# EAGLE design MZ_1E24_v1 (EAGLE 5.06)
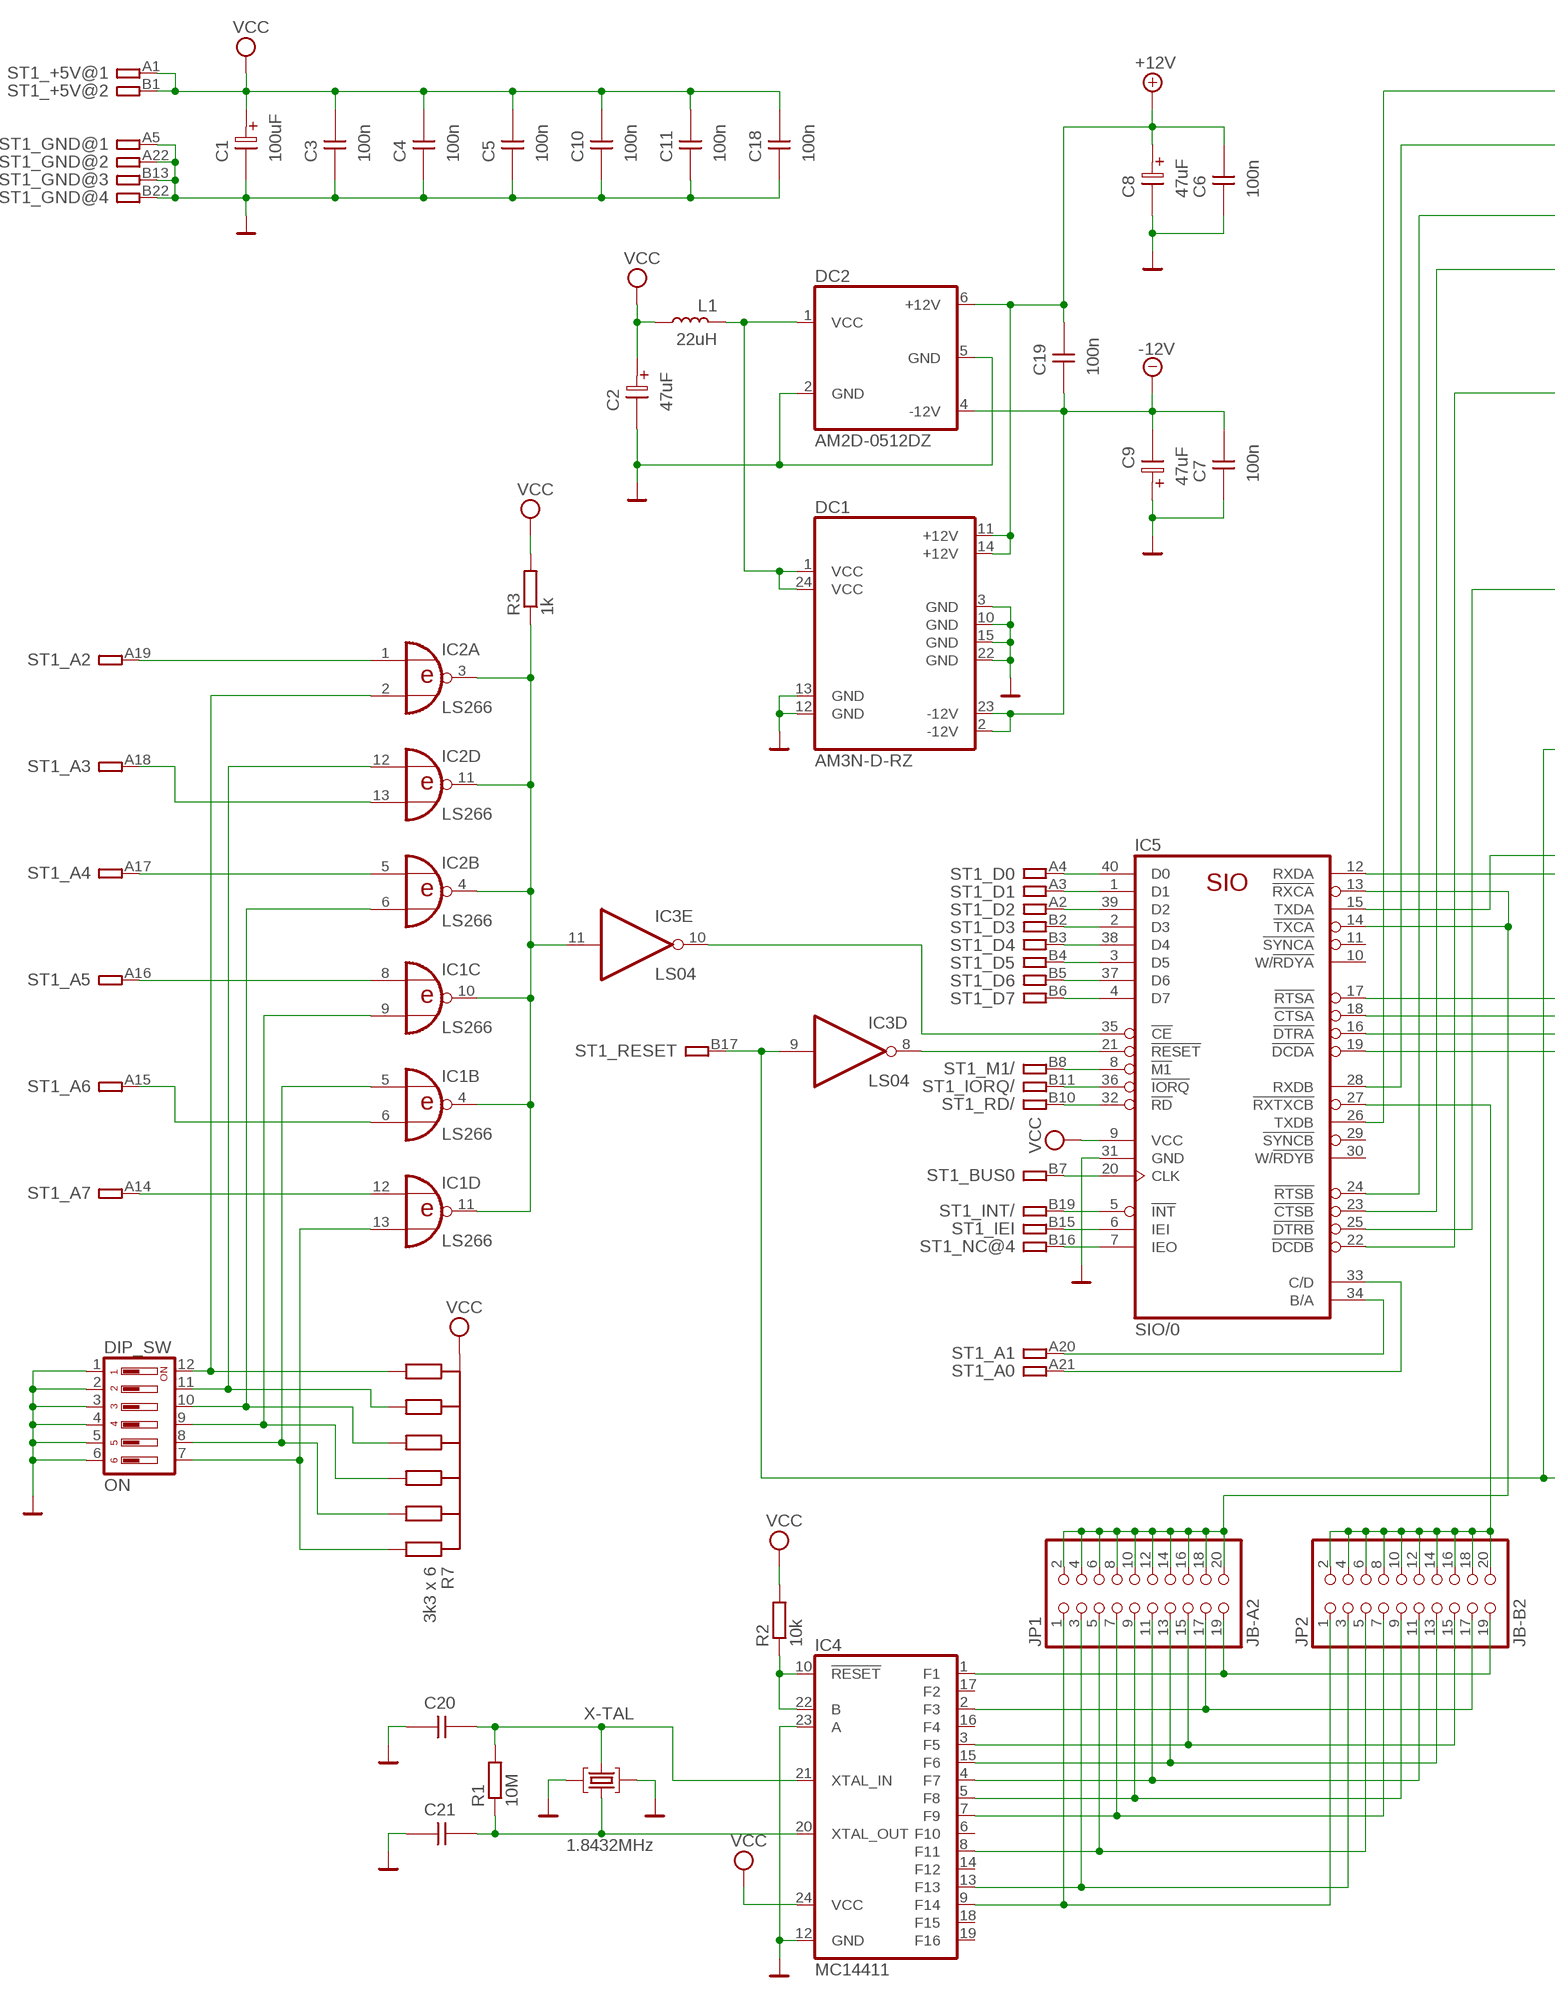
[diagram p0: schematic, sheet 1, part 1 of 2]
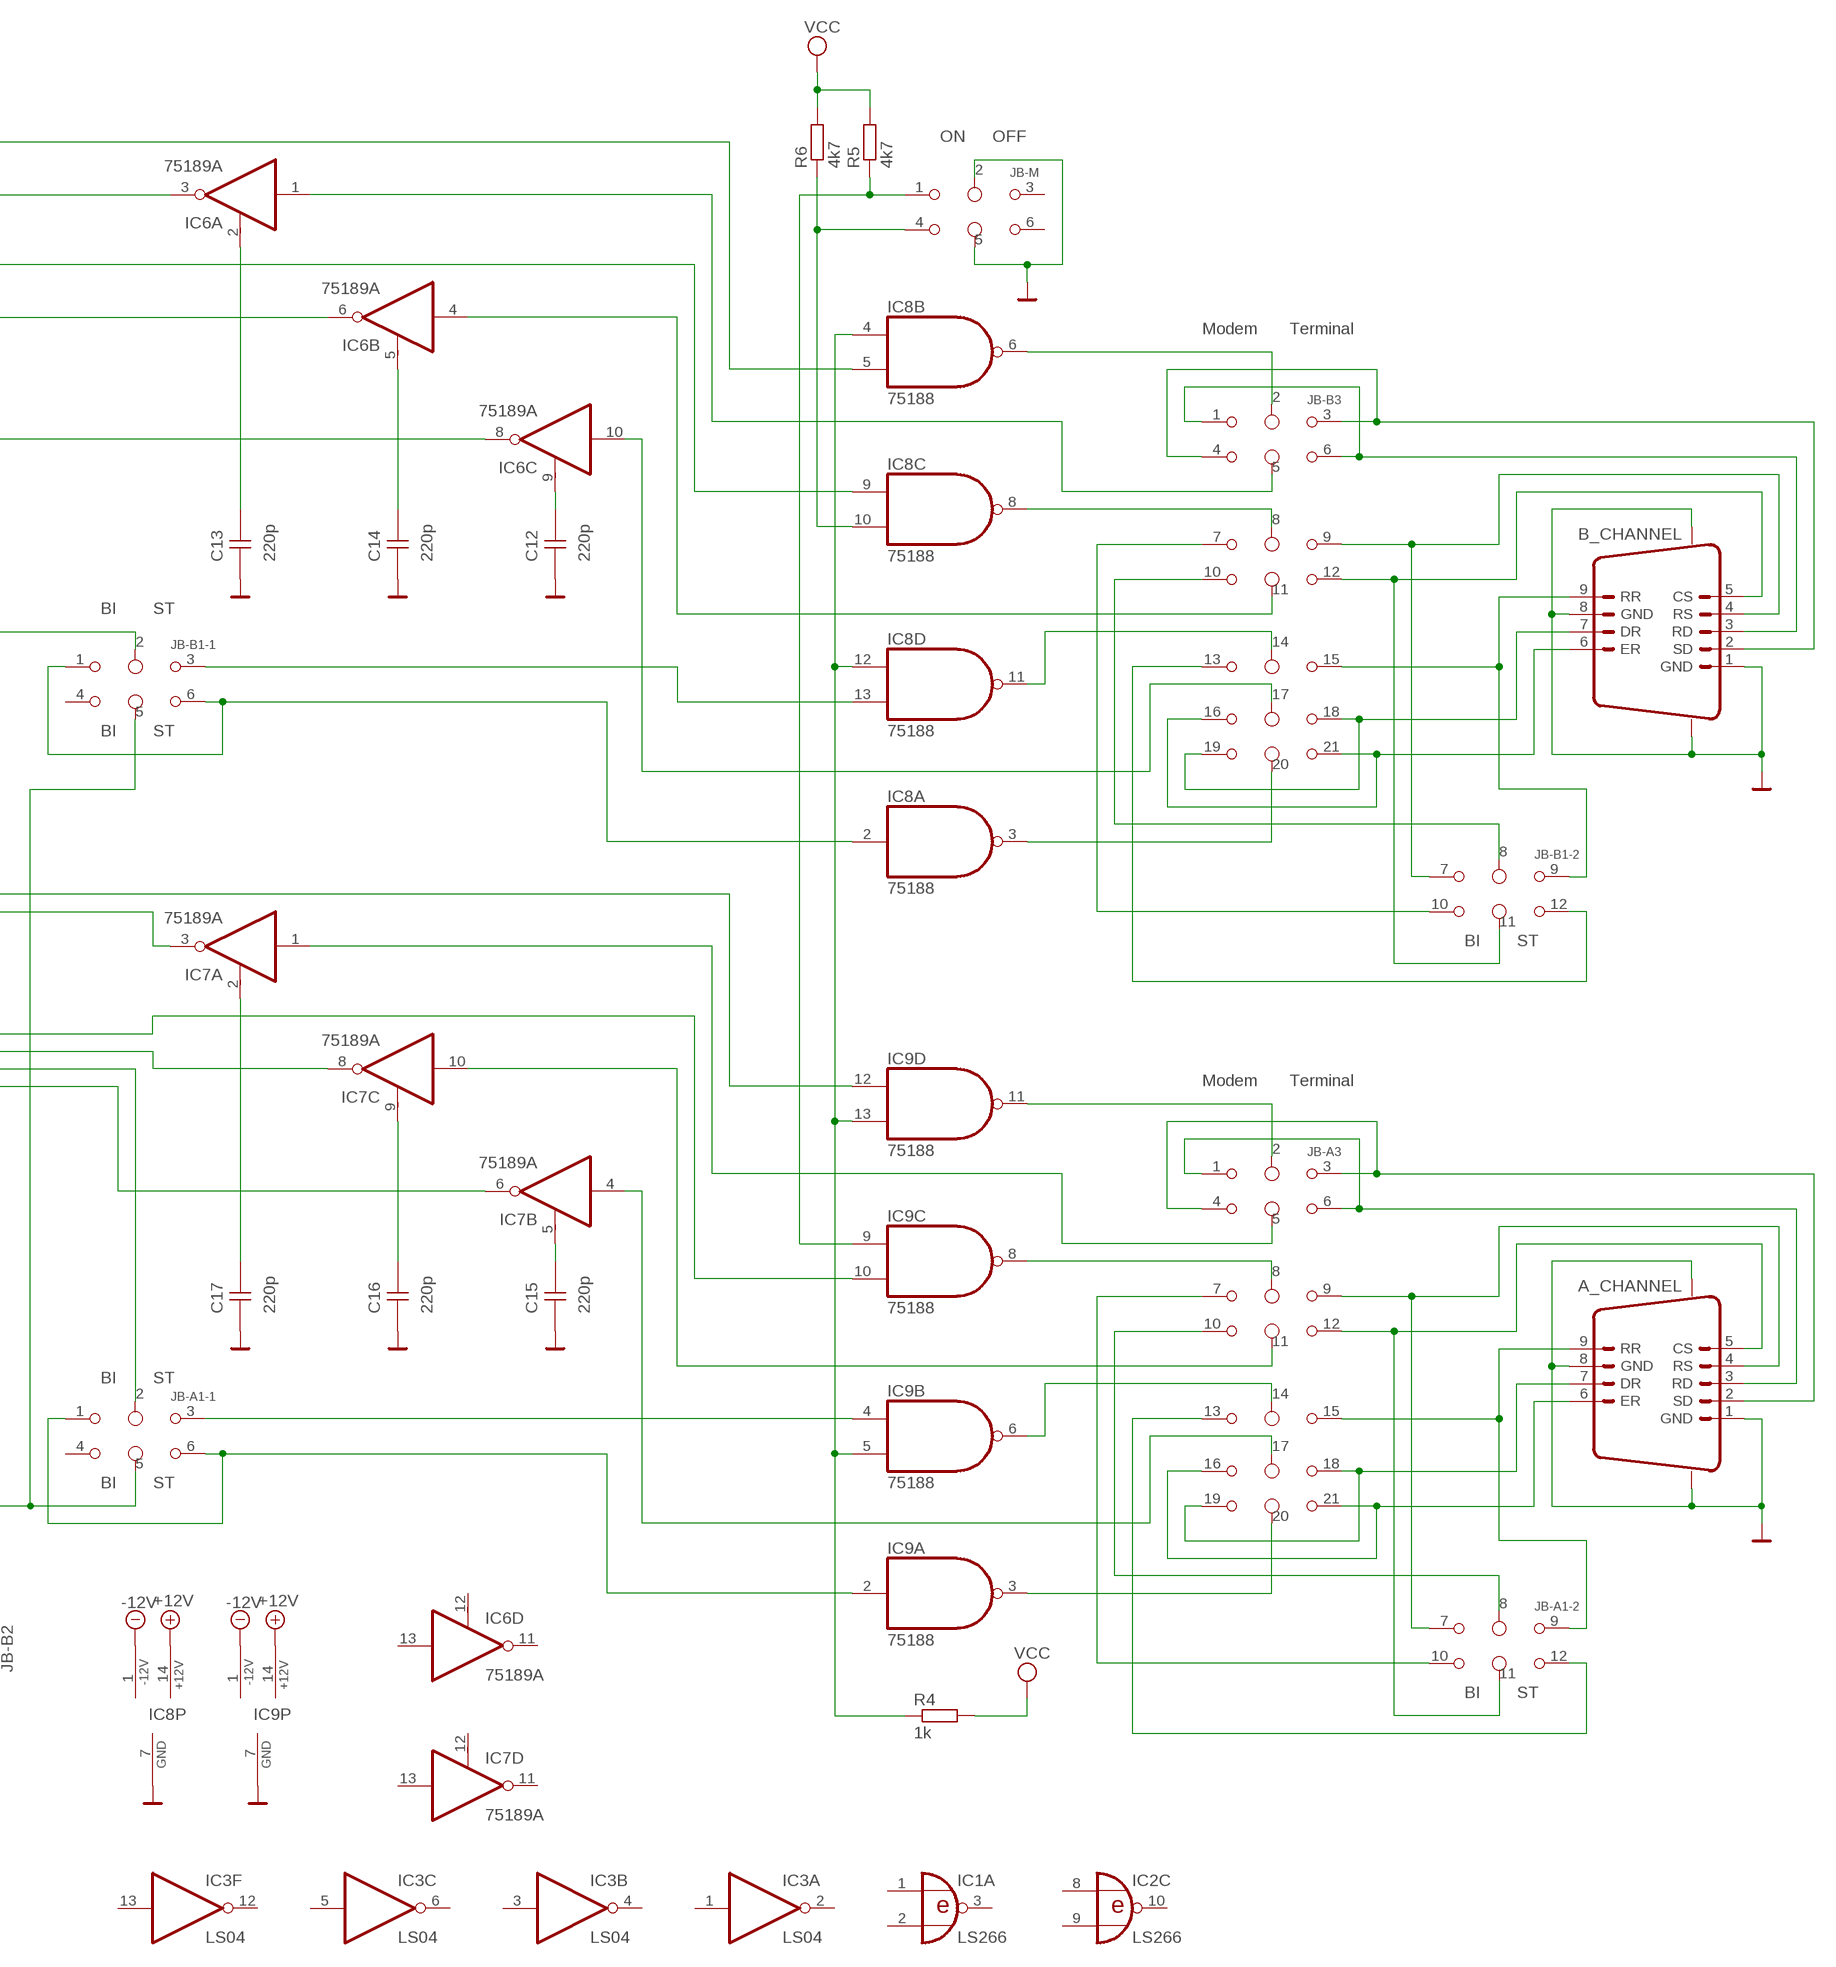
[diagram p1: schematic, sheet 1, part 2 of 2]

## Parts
A_CHANNEL  RS232_PC"  [RS232_F]
B_CHANNEL  RS232_PC"  [RS232_F]
C1  100uF  E6,3X11  [E63]
C2  47uF  E6,3X11  [E63]
C3  100n  CK  [CK]
C4  100n  CK  [CK]
C5  100n  CK  [CK]
C6  100n  CK  [CK]
C7  100n  CK  [CK]
C8  47uF  E6,3X11  [E63]
C9  47uF  E6,3X11  [E63]
C10  100n  CK  [CK]
C11  100n  CK  [CK]
C12  220p  CK  [CK]
C13  220p  CK  [CK]
C14  220p  CK  [CK]
C15  220p  CK  [CK]
C16  220p  CK  [CK]
C17  220p  CK  [CK]
C18  100n  CK  [CK]
C19  100n  CK  [CK]
C20  CK  [CK]
C21  CK  [CK]
DC1  AM3N-D-RZ  DC-DC_AM3N  [DC-DC_AM3N]
DC2  AM2D-0512DZ  DC-DC_AM1D  [DC-DC_AM1D]
DIP_SW  ON  SWITCH-DIL_DIP06YL  [SWITCH-DIL_DIP06YL]
IC1  LS266  74266  [DIL14]
IC2  LS266  74266  [DIL14]
IC3  LS04  74LS04N  [EU_DIL14]
IC4  MC14411  [DIL24]
IC5  SIO/0  Z80SIO0  [DIL40]
IC6  75189A  1489  [DIL14]
IC7  75189A  1489  [DIL14]
IC8  75188  1488N  [INTERFACE_DIL14]
IC9  75188  1488N  [INTERFACE_DIL14]
JB-A1  PINHD-4X3  [PINHD-4X3]
JB-A3  JB-A3  PINHD-7X3A  [PINHD-7X3A]
JB-B1  PINHD-4X3B  [PINHD-4X3B]
JB-B3  JB-B3  PINHD-7X3B  [PINHD-7X3B]
JB-M  JB-M  PINHD-2X3  [PINHD-2X3]
JP1  JB-A2  PINHD-2X10A  [PINHD-2X10A]
JP2  JB-B2  PINHD-2X10  [PINHD-2X10]
L1  22uH  L  [L]
R1  10M  R-EU_0204/5  [RCL_0204/5]
R2  10k  R-EU_0204/5  [RCL_0204/5]
R3  1k  R-EU_0204/5  [RCL_0204/5]
R4  1k  R-EU_0204/5  [RCL_0204/5]
R5  4k7  R-EU_0204/5  [RCL_0204/5]
R6  4k7  R-EU_0204/5  [RCL_0204/5]
R7  3k3 x 6  RR6X  [RR6X]
ST1  MZ800BUSSHORTN  [MZ800BUSSHORTN]
X-TAL  1.8432MHz  HC49TL-H  [HC49TL-H]

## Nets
+12V: C6.2 C8.1 C19.2 DC1.11(+12V) DC1.14(+12V) DC2.6(+12V) IC8.14(P:+12V) IC9.14(P:+12V)
-12V: C7.2 C9.2 C19.1 DC1.2(-12V) DC1.23(-12V) DC2.4(-12V) IC8.1(P:-12V) IC9.1(P:-12V)
A0: IC5.33(C/D) ST1.A21
A1: IC5.34(B/A) ST1.A20
A2: IC2.1(A:I0) ST1.A19
A4: IC2.5(B:I0) ST1.A17
A5: IC1.8(C:I0) ST1.A16
A7: IC1.12(D:I0) ST1.A14
A_CHANNEL: A_CHANNEL.7(DR) JB-A3.18 JB-A3.19
A_CHANNEL1: B_CHANNEL.7(DR) JB-B3.18 JB-B3.19
BUS0: IC5.20(CLK) ST1.B7
D0: IC5.40(D0) ST1.A4
D1: IC5.1(D1) ST1.A3
D2: IC5.39(D2) ST1.A2
D3: IC5.2(D3) ST1.B2
D4: IC5.38(D4) ST1.B3
D5: IC5.3(D5) ST1.B4
D6: IC5.37(D6) ST1.B5
D7: IC5.4(D7) ST1.B6
EXTINT: IC5.5(!INT) ST1.B19
GND: A_CHANNEL.1(GND) A_CHANNEL.8(GND) A_CHANNEL.P$1(GND) A_CHANNEL.P$2(GND) B_CHANNEL.1(GND) B_CHANNEL.8(GND) B_CHANNEL.P$1(GND) B_CHANNEL.P$2(GND) C1.2 C2.2 C3.1 C4.1 C5.1 C6.1 C7.1 C8.2 C9.1 C10.1 C11.1 C12.1 C13.1 C14.1 C15.1 C16.1 C17.1 C18.1 C20.1 C21.1 DC1.3(GND) DC1.10(GND) DC1.12(GND) DC1.13(GND) DC1.15(GND) DC1.22(GND) DC2.2(GND) DC2.5(GND) DIP_SW.1 DIP_SW.2 DIP_SW.3 DIP_SW.4 DIP_SW.5 DIP_SW.6 IC4.12(GND) IC4.23(A) IC5.31(GND) IC8.7(P:GND) IC9.7(P:GND) JB-M.2 JB-M.5 ST1.A5 ST1.A22 ST1.B13 ST1.B22 X-TAL.3 X-TAL.4 ; supply symbol labelled gnd
IEI: IC5.6(IEI) ST1.B15
IEO: IC5.7(IEO) ST1.B16
IORQ: IC5.36(!IORQ) ST1.B11
M1: IC5.8(!M1) ST1.B8
N$1: IC1.4(B:O) IC1.10(C:O) IC1.11(D:O) IC2.3(A:O) IC2.4(B:O) IC2.11(D:O) IC3.11(E:I) R3.1
N$2: IC3.8(D:O) IC5.21(!RESET)
N$3: IC5.27(!RXTXCB) JP2.2 JP2.4 JP2.6 JP2.8 JP2.10 JP2.12 JP2.14 JP2.16 JP2.18 JP2.20
N$4: IC5.13(!RXCA) IC5.14(!TXCA) JP1.2 JP1.4 JP1.6 JP1.8 JP1.10 JP1.12 JP1.14 JP1.16 JP1.18 JP1.20
N$5: C21.2 IC4.20(XTAL_OUT) R1.1 X-TAL.1
N$6: C20.2 IC4.21(XTAL_IN) R1.2 X-TAL.2
N$7: DIP_SW.12 IC2.2(A:I1) R7.7
N$8: DIP_SW.11 IC2.12(D:I0) R7.6
N$9: DIP_SW.10 IC2.6(B:I1) R7.5
N$10: DIP_SW.9 IC1.9(C:I1) R7.4
N$11: DIP_SW.8 IC1.5(B:I0) R7.3
N$12: DIP_SW.7 IC1.13(D:I1) R7.2
N$13: C15.2 IC7.5(B:RC)
N$14: C16.2 IC7.9(C:RC)
N$15: C17.2 IC7.2(A:RC)
N$16: C12.2 IC6.9(C:RC)
N$17: C14.2 IC6.5(B:RC)
N$18: C13.2 IC6.2(A:RC)
N$19: IC4.9(F14) JP1.1 JP2.1
N$20: IC4.13(F13) JP1.3 JP2.3
N$21: IC4.8(F11) JP1.5 JP2.5
N$22: IC4.7(F9) JP1.7 JP2.7
N$23: IC4.5(F8) JP1.9 JP2.9
N$24: IC4.4(F7) JP1.11 JP2.11
N$25: IC4.15(F6) JP1.13 JP2.13
N$26: IC4.3(F5) JP1.15 JP2.15
N$27: IC4.2(F3) JP1.17 JP2.17
N$28: IC4.1(F1) JP1.19 JP2.19
N$29: IC3.10(E:O) IC5.35(!CE)
N$30: IC4.10(!RESET) IC4.22(B) R2.1
N$31: IC9.6(B:O) JB-A3.14
N$32: DC1.1(VCC) DC1.24(VCC) DC2.1(VCC) L1.1
N$33: IC8.2(A:I) JB-B1.1 JB-B1.6
N$34: IC8.4(B:I0) IC8.12(D:I0) IC9.5(B:I1) IC9.13(D:I1) R4.1
N$35: IC9.3(A:O) JB-A3.20
N$37: A_CHANNEL.6(ER) JB-A3.16 JB-A3.21
N$38: IC7.4(B:I) JB-A3.17
N$39: IC9.8(C:O) JB-A3.8
N$40: IC9.11(D:O) JB-A3.2
N$41: A_CHANNEL.3(RD) JB-A3.1 JB-A3.6
N$42: A_CHANNEL.2(SD) JB-A3.3 JB-A3.4
N$43: IC7.1(A:I) JB-A3.5
N$44: IC7.10(C:I) JB-A3.11
N$45: A_CHANNEL.4(RS) JB-A1.7 JB-A3.9
N$46: A_CHANNEL.5(CS) JB-A1.11 JB-A3.12
N$47: A_CHANNEL.9(RR) JB-A1.9 JB-A3.15
N$48: JB-A1.12 JB-A3.13
N$49: IC5.15(TXDA) IC9.12(D:I0)
N$50: JB-A1.10 JB-A3.7
N$51: JB-A1.8 JB-A3.10
N$52: IC5.12(RXDA) IC7.3(A:O)
N$53: IC5.17(!RTSA) IC9.10(C:I1)
N$54: IC9.4(B:I0) JB-A1.3
N$55: IC5.18(!CTSA) IC7.8(C:O)
N$56: IC5.19(!DCDA) IC7.6(B:O)
N$57: IC9.2(A:I) JB-A1.1 JB-A1.6
N$58: IC5.16(!DTRA) JB-A1.2
N$59: IC2.13(D:I1) ST1.A18
N$60: IC1.6(B:I1) ST1.A15
N$67: IC8.13(D:I1) JB-B1.3
N$75: IC8.10(C:I1) JB-M.4 R6.1
N$80: IC9.9(C:I0) JB-M.1 R5.1
N$84: IC8.3(A:O) JB-B3.20
N$85: B_CHANNEL.6(ER) JB-B3.16 JB-B3.21
N$86: IC6.10(C:I) JB-B3.17
N$87: IC8.11(D:O) JB-B3.14
N$88: IC8.8(C:O) JB-B3.8
N$89: IC8.6(B:O) JB-B3.2
N$90: B_CHANNEL.3(RD) JB-B3.1 JB-B3.6
N$91: B_CHANNEL.2(SD) JB-B3.3 JB-B3.4
N$92: IC6.1(A:I) JB-B3.5
N$93: IC6.4(B:I) JB-B3.11
N$94: B_CHANNEL.4(RS) JB-B1.7 JB-B3.9
N$95: B_CHANNEL.5(CS) JB-B1.11 JB-B3.12
N$96: B_CHANNEL.9(RR) JB-B1.9 JB-B3.15
N$97: JB-B1.12 JB-B3.13
N$98: JB-B1.10 JB-B3.7
N$99: JB-B1.8 JB-B3.10
N$100: IC5.26(TXDB) IC8.5(B:I1)
N$101: IC5.28(RXDB) IC6.3(A:O)
N$102: IC5.24(!RTSB) IC8.9(C:I0)
N$104: IC5.23(!CTSB) IC6.6(B:O)
N$105: IC5.22(!DCDB) IC6.8(C:O)
N$107: IC5.25(!DTRB) JB-B1.2
RD: IC5.32(!RD) ST1.B10
RESET: IC3.9(D:I) JB-A1.5 JB-B1.5 ST1.B17
VCC: C1.1 C2.1 C3.2 C4.2 C5.2 C10.2 C11.2 C18.2 IC4.24(VCC) IC5.9(VCC) L1.2 R2.2 R3.2 R4.2 R5.2 R6.2 R7.1 ST1.A1 ST1.B1
Unconnected: IC1.1(A:I0) IC1.2(A:I1) IC1.3(A:O) IC2.8(C:I0) IC2.9(C:I1) IC2.10(C:O) IC3.1(A:I) IC3.2(A:O) IC3.3(B:I) IC3.4(B:O) IC3.5(C:I) IC3.6(C:O) IC3.12(F:O) IC3.13(F:I) IC4.6(F10) IC4.14(F12) IC4.16(F4) IC4.17(F2) IC4.18(F15) IC4.19(F16) IC5.10(W/!RDYA) IC5.11(!SYNCA) IC5.29(!SYNCB) IC5.30(W/!RDYB) IC6.11(D:O) IC6.12(D:RC) IC6.13(D:I) IC7.11(D:O) IC7.12(D:RC) IC7.13(D:I) JB-A1.4 JB-B1.4 JB-M.3 JB-M.6 ST1.A6 ST1.A7 ST1.A8 ST1.A9 ST1.A10 ST1.A11 ST1.A12 ST1.A13 ST1.B9 ST1.B12 ST1.B14 ST1.B18 ST1.B20 ST1.B21

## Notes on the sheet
- ON | OFF
- Modem | Terminal
- BI | ST
- BI | ST
- BI | ST
- Modem | Terminal
- BI | ST
- BI | ST
- BI | ST

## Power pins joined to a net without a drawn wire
GND: IC1.7(P:GND) IC2.7(P:GND) IC3.7(P:GND) IC6.7(P:GND) IC7.7(P:GND)
VCC: IC1.14(P:VCC) IC2.14(P:VCC) IC3.14(P:VCC) IC6.14(P:VCC) IC7.14(P:VCC)

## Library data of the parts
A_CHANNEL B_CHANNEL = MZ_1E24:RS232_PC
C1 C2 C8 C9 = MZ_1E24:E6,3X11
C3-C7 C10-C21 = MZ_1E24:CK
DC1 = MZ_1E24:DC-DC_AM3N
DC2 = MZ_1E24:DC-DC_AM1D
DIP_SW = MZ_1E24:SWITCH-DIL_DIP06YL: DIL/CODE SWITCH
IC1 IC2 = MZ_1E24:74*266: Quadruple EXCLUSIVE-NOR (XNOR), open-collector
IC3 = MZ_1E24:74*04: Hex INVERTER
IC4 = MZ_1E24:MC14411
IC5 = MZ_1E24:Z80SIO0: Z80 FAMILY DEVICE
IC6 IC7 = MZ_1E24:14*89: Quad line receivers BUFFER,
IC8 IC9 = MZ_1E24:14*88: Quad 2-input NAND gate
JB-A1 JB-B1 = MZ_1E24:PINHD-4X3
JB-A3 JB-B3 = MZ_1E24:PINHD-7X3
JB-M = MZ_1E24:PINHD-2X3
JP1 JP2 = MZ_1E24:PINHD-2X10: PIN HEADER
L1 = MZ_1E24:L
R1-R6 = MZ_1E24:R-EU_: RESISTOR, European symbol
R7 = MZ_1E24:RR6X
ST1 = MZ_1E24:MZ800BUSSHORT: 44-bit BUS for MZ800
X-TAL = MZ_1E24:HC49TL-H: CRYSTAL

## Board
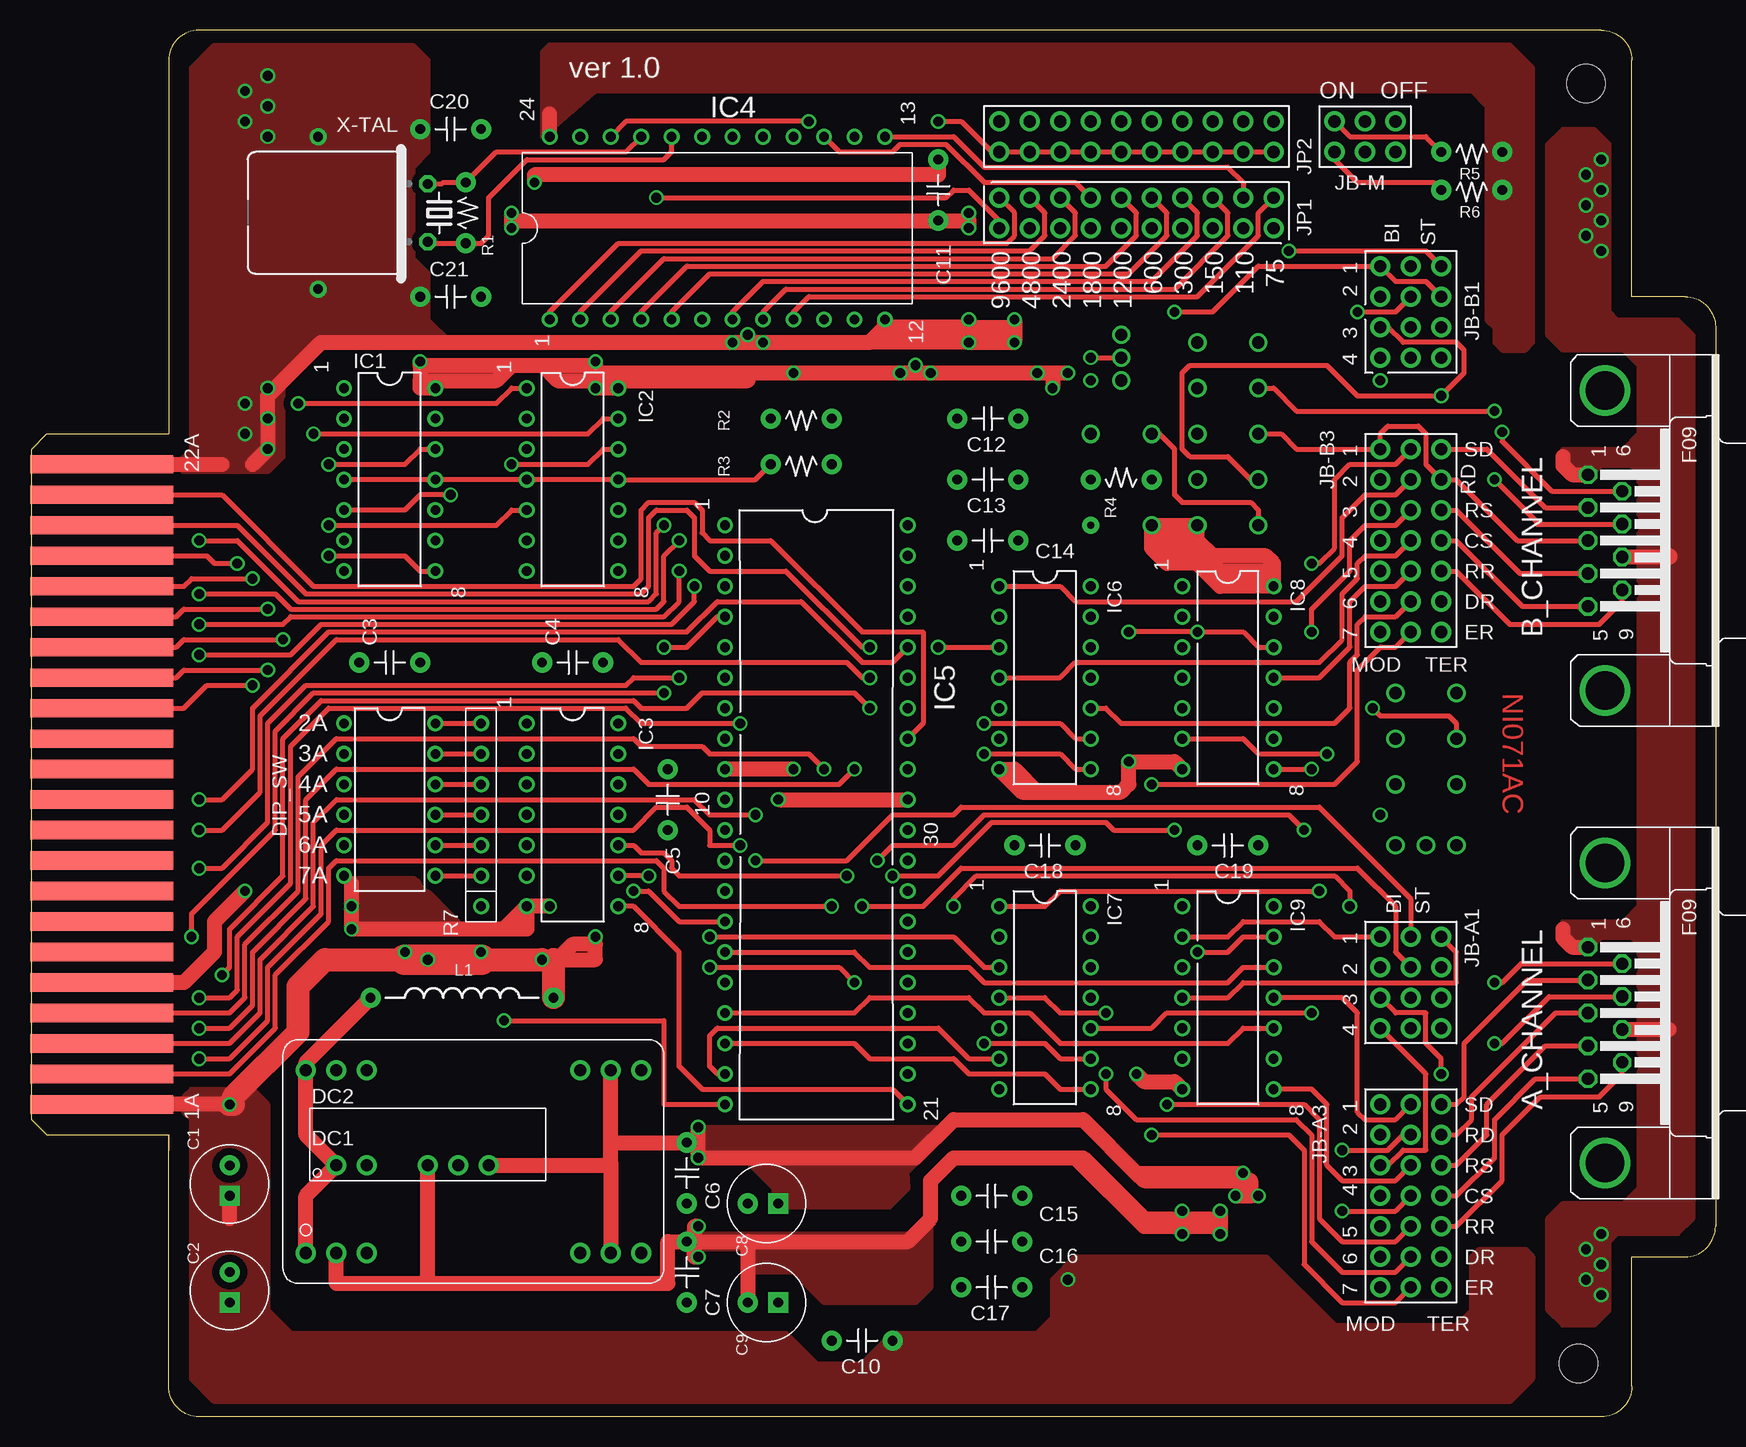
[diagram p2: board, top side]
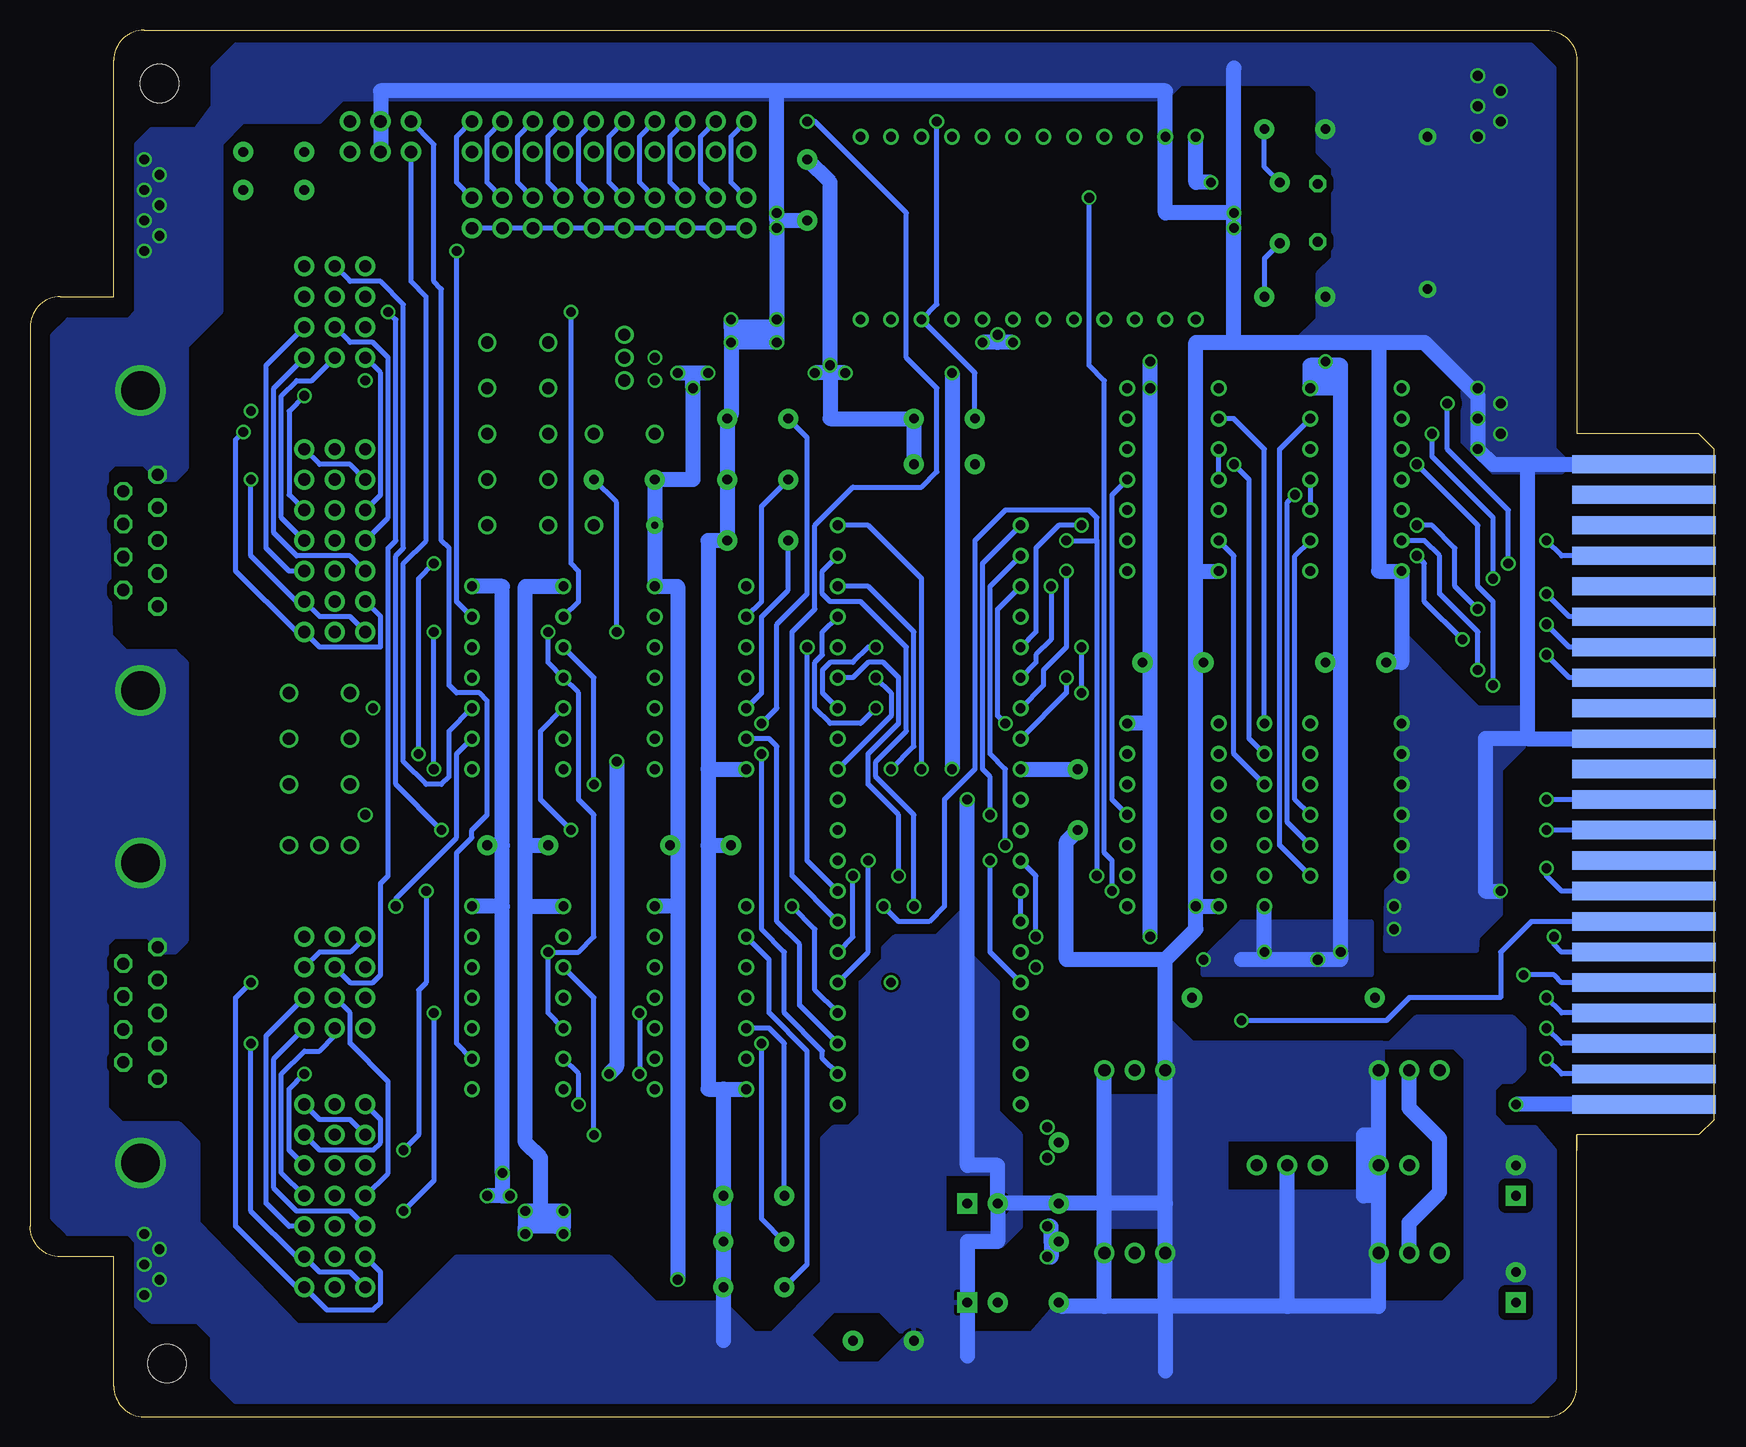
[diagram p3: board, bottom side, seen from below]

Size 140.34 x 115.57 mm. Coordinates in mm from the lower left corner, seen from the top.
Outline: 11.43,89.53 11.43,113.03 arc-90 13.97,115.57 130.81,115.57 arc-90 133.35,113.03 133.35,93.34 137.8,93.34 arc-90 140.34,90.81 140.34,15.88 arc-90 137.8,13.34 133.35,13.34 133.35,2.54 arc-90 130.81,0 13.97,0 arc-90 11.43,2.54 11.43,23.5
Copper layers (1*16): Top 0.035mm / dielectric 1.5mm / Bottom 0.035mm
Design rules "MZ_1E24 *": minimum track width 6mil, minimum drill 12mil, track to track 8mil, track to pad 8mil, pad to pad 8mil, via to via 8mil, smd to smd 0mil, copper to edge 10mil, drill to drill 10mil, minimum pad ring 10mil, minimum via ring 6mil, stop-mask expansion 2mil, vias tented up to drill 100mil, thermal gap 10mil
Holes 3.2 mm at 129.54,111.12 128.91,4.45

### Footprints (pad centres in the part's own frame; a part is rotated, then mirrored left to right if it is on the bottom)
RS232_F = drill 1.016 octagon: 1 -5.486,0.794; 2 -2.743,0.794; 3 0,0.794; 4 2.743,0.794; 5 5.486,0.794; 6 -4.115,3.651; 7 -1.372,3.651; 8 1.371,3.651; 9 4.115,3.651 | drill 3.2 round: P$1 -12.502,2.223; P$2 12.502,2.223
E63 = drill 0.813 pad 1.676 square: 1 0,0 | drill 0.813 pad 1.676 round: 2 2.54,0
CK = drill 0.813 pad 1.676 round: 1 0,0; 2 5.08,0
DC-DC_AM3N = drill 1.016 pad 1.676 round: 1 1.905,2.54; 2 4.445,2.54; 3 6.985,2.54; 10 24.765,2.54; 11 27.305,2.54; 12 29.845,2.54; 13 29.845,17.78; 14 27.305,17.78; 15 24.765,17.78; 22 6.985,17.78; 23 4.445,17.78; 24 1.905,17.78
DC-DC_AM1D = drill 1.016 pad 1.676 round: 1 2.223,1.27; 2 4.763,1.27; 4 9.842,1.27; 5 12.383,1.27; 6 14.922,1.27
SWITCH-DIL_DIP06YL = drill 0.813 round: 1 -6.35,-3.81; 2 -3.81,-3.81; 3 -1.27,-3.81; 4 1.27,-3.81; 5 3.81,-3.81; 6 6.35,-3.81; 7 6.35,3.81; 8 3.81,3.81; 9 1.27,3.81; 10 -1.27,3.81; 11 -3.81,3.81; 12 -6.35,3.81
DIL14 = drill 0.813 round: 1 -7.62,-3.81; 2 -5.08,-3.81; 3 -2.54,-3.81; 4 0,-3.81; 5 2.54,-3.81; 6 5.08,-3.81; 7 7.62,-3.81; 8 7.62,3.81; 9 5.08,3.81; 10 2.54,3.81; 11 0,3.81; 12 -2.54,3.81; 13 -5.08,3.81; 14 -7.62,3.81
EU_DIL14 = drill 0.813 round: 1 -7.62,-3.81; 2 -5.08,-3.81; 3 -2.54,-3.81; 4 0,-3.81; 5 2.54,-3.81; 6 5.08,-3.81; 7 7.62,-3.81; 8 7.62,3.81; 9 5.08,3.81; 10 2.54,3.81; 11 0,3.81; 12 -2.54,3.81; 13 -5.08,3.81; 14 -7.62,3.81
DIL24 = drill 0.813 round: 1 -13.97,-7.62; 2 -11.43,-7.62; 3 -8.89,-7.62; 4 -6.35,-7.62; 5 -3.81,-7.62; 6 -1.27,-7.62; 7 1.27,-7.62; 8 3.81,-7.62; 9 6.35,-7.62; 10 8.89,-7.62; 11 11.43,-7.62; 12 13.97,-7.62; 13 13.97,7.62; 14 11.43,7.62; 15 8.89,7.62; 16 6.35,7.62; 17 3.81,7.62; 18 1.27,7.62; 19 -1.27,7.62; 20 -3.81,7.62; 21 -6.35,7.62; 22 -8.89,7.62; 23 -11.43,7.62; 24 -13.97,7.62
DIL40 = drill 0.813 round: 1 -24.13,-7.62; 2 -21.59,-7.62; 3 -19.05,-7.62; 4 -16.51,-7.62; 5 -13.97,-7.62; 6 -11.43,-7.62; 7 -8.89,-7.62; 8 -6.35,-7.62; 9 -3.81,-7.62; 10 -1.27,-7.62; 11 1.27,-7.62; 12 3.81,-7.62; 13 6.35,-7.62; 14 8.89,-7.62; 15 11.43,-7.62; 16 13.97,-7.62; 17 16.51,-7.62; 18 19.05,-7.62; 19 21.59,-7.62; 20 24.13,-7.62; 21 24.13,7.62; 22 21.59,7.62; 23 19.05,7.62; 24 16.51,7.62; 25 13.97,7.62; 26 11.43,7.62; 27 8.89,7.62; 28 6.35,7.62; 29 3.81,7.62; 30 1.27,7.62; 31 -1.27,7.62; 32 -3.81,7.62; 33 -6.35,7.62; 34 -8.89,7.62; 35 -11.43,7.62; 36 -13.97,7.62; 37 -16.51,7.62; 38 -19.05,7.62; 39 -21.59,7.62; 40 -24.13,7.62
INTERFACE_DIL14 = drill 0.813 round: 1 -7.62,-3.81; 2 -5.08,-3.81; 3 -2.54,-3.81; 4 0,-3.81; 5 2.54,-3.81; 6 5.08,-3.81; 7 7.62,-3.81; 8 7.62,3.81; 9 5.08,3.81; 10 2.54,3.81; 11 0,3.81; 12 -2.54,3.81; 13 -5.08,3.81; 14 -7.62,3.81
PINHD-4X3 = drill 1.016 pad 1.676 round: 1 -2.54,3.81; 2 0,3.81; 3 2.54,3.81; 4 -2.54,1.27; 5 0,1.27; 6 2.54,1.27; 7 -2.54,-1.27; 8 0,-1.27; 9 2.54,-1.27; 10 -2.54,-3.81; 11 0,-3.81; 12 2.54,-3.81
PINHD-7X3A = drill 1.016 pad 1.676 round: 1 -2.54,7.62; 2 0,7.62; 3 2.54,7.62; 4 -2.54,5.08; 5 0,5.08; 6 2.54,5.08; 7 -2.54,2.54; 8 0,2.54; 9 2.54,2.54; 10 -2.54,0; 11 0,0; 12 2.54,0; 13 -2.54,-2.54; 14 0,-2.54; 15 2.54,-2.54; 16 -2.54,-5.08; 17 0,-5.08; 18 2.54,-5.08; 19 -2.54,-7.62; 20 0,-7.62; 21 2.54,-7.62
PINHD-4X3B = drill 1.016 pad 1.676 round: 1 -2.54,3.81; 2 0,3.81; 3 2.54,3.81; 4 -2.54,1.27; 5 0,1.27; 6 2.54,1.27; 7 -2.54,-1.27; 8 0,-1.27; 9 2.54,-1.27; 10 -2.54,-3.81; 11 0,-3.81; 12 2.54,-3.81
PINHD-7X3B = drill 1.016 pad 1.676 round: 1 -2.54,7.62; 2 0,7.62; 3 2.54,7.62; 4 -2.54,5.08; 5 0,5.08; 6 2.54,5.08; 7 -2.54,2.54; 8 0,2.54; 9 2.54,2.54; 10 -2.54,0; 11 0,0; 12 2.54,0; 13 -2.54,-2.54; 14 0,-2.54; 15 2.54,-2.54; 16 -2.54,-5.08; 17 0,-5.08; 18 2.54,-5.08; 19 -2.54,-7.62; 20 0,-7.62; 21 2.54,-7.62
PINHD-2X3 = drill 1.016 pad 1.676 round: 1 -2.54,1.27; 2 0,1.27; 3 2.54,1.27; 4 -2.54,-1.27; 5 0,-1.27; 6 2.54,-1.27
PINHD-2X10A = drill 1.016 pad 1.676 round: 1 -11.43,-1.27; 2 -11.43,1.27; 3 -8.89,-1.27; 4 -8.89,1.27; 5 -6.35,-1.27; 6 -6.35,1.27; 7 -3.81,-1.27; 8 -3.81,1.27; 9 -1.27,-1.27; 10 -1.27,1.27; 11 1.27,-1.27; 12 1.27,1.27; 13 3.81,-1.27; 14 3.81,1.27; 15 6.35,-1.27; 16 6.35,1.27; 17 8.89,-1.27; 18 8.89,1.27; 19 11.43,-1.27; 20 11.43,1.27
PINHD-2X10 = drill 1.016 pad 1.676 round: 1 -11.43,-1.27; 2 -11.43,1.27; 3 -8.89,-1.27; 4 -8.89,1.27; 5 -6.35,-1.27; 6 -6.35,1.27; 7 -3.81,-1.27; 8 -3.81,1.27; 9 -1.27,-1.27; 10 -1.27,1.27; 11 1.27,-1.27; 12 1.27,1.27; 13 3.81,-1.27; 14 3.81,1.27; 15 6.35,-1.27; 16 6.35,1.27; 17 8.89,-1.27; 18 8.89,1.27; 19 11.43,-1.27; 20 11.43,1.27
L = drill 0.813 pad 1.676 round: 1 -7.62,0; 2 7.62,0
RCL_0204/5 = drill 0.813 pad 1.676 round: 1 -2.54,0; 2 2.54,0
RR6X = drill 0.813 round: 1 0,0; 2 2.54,0; 3 5.08,0; 4 7.62,0; 5 10.16,0; 6 12.7,0; 7 15.24,0
MZ800BUSSHORTN = smd 1.524 x 11.938: A1 64.77,-4.318; A2 62.23,-4.318; A3 59.69,-4.318; A4 57.15,-4.318; A5 54.61,-4.318; A6 52.07,-4.318; A7 49.53,-4.318; A8 46.99,-4.318; A9 44.45,-4.318; A10 41.91,-4.318; A11 39.37,-4.318; A12 36.83,-4.318; A13 34.29,-4.318; A14 31.75,-4.318; A15 29.21,-4.318; A16 26.67,-4.318; A17 24.13,-4.318; A18 21.59,-4.318; A19 19.05,-4.318; A20 16.51,-4.318; A21 13.97,-4.318; A22 11.43,-4.318 | smd 1.524 x 11.938 bottom: B1 64.77,-4.318; B2 62.23,-4.318; B3 59.69,-4.318; B4 57.15,-4.318; B5 54.61,-4.318; B6 52.07,-4.318; B7 49.53,-4.318; B8 46.99,-4.318; B9 44.45,-4.318; B10 41.91,-4.318; B11 39.37,-4.318; B12 36.83,-4.318; B13 34.29,-4.318; B14 31.75,-4.318; B15 29.21,-4.318; B16 26.67,-4.318; B17 24.13,-4.318; B18 21.59,-4.318; B19 19.05,-4.318; B20 16.51,-4.318; B21 13.97,-4.318; B22 11.43,-4.318
HC49TL-H = drill 0.813 pad 1.422 octagon: 1 -2.413,-7.62; 2 2.413,-7.62 | drill 0.813 pad 1.422 round: 3 6.35,1.524; 4 -6.35,1.524

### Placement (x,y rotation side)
A_CHANNEL  128.91,33.66 270 top
B_CHANNEL  128.91,73.03 270 top
C1  16.51,18.41 90 top
C2  16.51,9.53 90 top
C3  27.3,62.87 0 top
C4  42.55,62.87 0 top
C5  53.02,48.9 90 top
C6  54.61,17.78 90 top
C7  54.61,9.53 90 top
C8  62.23,17.78 180 top
C9  62.23,9.53 180 top
C10  66.67,6.35 0 top
C11  75.56,99.69 90 top
C12  82.23,83.19 180 top
C13  82.23,78.11 180 top
C14  82.23,73.03 180 top
C15  82.55,18.41 180 top
C16  82.55,14.61 180 top
C17  82.55,10.79 180 top
C18  81.91,47.62 0 top
C19  97.16,47.62 0 top
C20  32.39,107.31 0 top
C21  32.39,93.34 0 top
DC1  20.95,11.11 0 top
DC2  23.18,19.68 0 top
DIP_SW  29.84,51.44 270 top
IC1  29.84,78.11 270 top
IC2  45.09,78.11 270 top
IC3  45.09,50.16 270 top
IC4  57.15,99.06 0 top
IC5  65.41,50.16 270 top
IC6  84.45,61.59 270 top
IC7  84.45,34.92 270 top
IC8  99.69,61.59 270 top
IC9  99.69,34.92 270 top
JB-A1  114.93,36.2 0 top
JB-A3  114.93,18.41 0 top
JB-B1  114.93,92.08 0 top
JB-B3  114.93,73.03 0 top
JB-M  111.12,106.68 0 top
JP1  92.07,100.33 180 top
JP2  92.07,106.68 180 top
L1  35.88,34.92 0 top
R1  36.2,100.33 90 top
R2  64.13,83.19 0 top
R3  64.13,79.38 0 top
R4  90.8,78.11 180 top
R5  120.02,105.41 0 top
R6  120.02,102.23 0 top
R7  37.47,42.55 90 top
ST1  10.16,90.81 270 top
X-TAL  25.4,100.33 90 top

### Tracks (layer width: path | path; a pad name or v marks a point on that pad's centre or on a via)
+12V  (via drill 0.81, 1.02)
  Top 0.406: 48.26,20.95 48.26,21.27
  Top 1.27: v55.56,24.13 v55.56,21.59 73.66,21.59 76.83,24.77 87.63,24.77 92.07,20.32 | 92.07,20.32 v100.96,20.32 | 92.07,20.32 92.71,19.68 100.96,19.68 | 100.96,19.68 100.96,18.41 | v100.33,18.41 100.96,18.41 | v102.23,18.41 101.6,18.41 | 100.96,19.68 101.6,19.68 101.6,18.41 | 100.96,18.41 101.6,18.41 | 103.5,70.48 103.5,71.12 102.87,71.75 98.42,71.75 97.16,73.03 v97.16,74.3 v93.34,74.3 93.34,72.39 94.61,71.12 97.16,71.12 99.06,69.22 IC8.14 103.5,70.48 | 103.5,70.48 99.06,70.48 97.16,72.39 | 97.16,72.39 96.52,73.03 93.98,73.03 94.61,72.39 97.16,72.39 | DC1.11 48.26,21.27 48.26,22.86 | 48.26,22.86 DC1.14 | DC2.6 48.26,20.95 | 48.26,22.86 C6.2
  Bottom 1.27: 100.96,42.55 v100.96,20.32 100.96,18.41 | 100.96,42.55 100.96,47.62 | 100.96,47.62 100.96,69.22 IC8.14 | 100.96,18.41 v100.33,18.41 | 100.96,18.41 v102.23,18.41 | 100.96,47.62 C19.2 | 100.96,42.55 IC9.14
  pour Top (isolate 0.61, no thermals): 55.25,24.13 76.83,24.13 72.95,20.36 73.02,19.05 71.44,17.46 61.91,17.46 61.91,19.05 59.37,21.59 55.25,21.59
-12V  (via drill 0.81)
  Top 1.27: 55.25,14.61 59.69,14.61 | 59.69,14.61 73.02,14.61 74.93,16.51 74.93,19.68 76.83,21.59 86.99,21.59 | 86.99,21.59 87.63,21.59 92.71,16.51 | 92.71,16.51 95.88,16.51 | 95.88,16.51 v95.88,17.14 | 95.88,16.51 99.06,16.51 v99.06,17.14 v99.06,15.24 99.06,15.88 95.88,15.88 | v55.56,13.34 55.25,13.34 55.25,14.61 | v55.56,15.88 55.25,15.88 55.25,14.61 | 95.88,15.88 v95.88,15.24 | 95.88,16.51 95.88,15.88 | 93.34,15.88 95.88,15.88 | 93.34,15.88 92.71,16.51 | 93.34,15.88 92.71,15.88 86.99,21.59 | 59.69,14.61 C9.2 | C7.2 53.02,14.61 53.02,11.11 33.02,11.11 | 33.02,11.11 25.4,11.11 DC1.2 | 33.02,11.11 DC2.4
  Bottom 1.27: v99.06,17.14 97.79,17.14 97.79,21.59 99.06,22.86 99.06,42.55 | 99.06,42.55 99.06,47.62 | 99.06,47.62 99.06,69.22 IC8.1 | v99.06,17.14 v95.88,17.14 95.88,16.51 | 95.88,16.51 95.88,15.88 | v95.88,15.24 95.88,15.88 | v99.06,15.24 99.06,15.88 | v99.06,17.14 99.06,15.88 | 95.88,16.51 96.52,15.88 | 96.52,15.88 99.06,15.88 | 95.88,15.88 96.52,15.88 | C7.2 55.25,14.61 | 55.25,14.61 55.25,15.88 v55.56,15.88 | 55.25,14.61 55.25,13.34 v55.56,13.34 | 99.06,47.62 C19.1 | 99.06,42.55 IC9.1 | DC1.23 25.4,25.72 22.86,23.18 22.86,18.73 25.4,16.19 DC1.2
  pour Top (isolate 0.61, no thermals): 55.25,14.61 55.25,15.24 73.66,15.24 74.93,16.51 74.93,10.79 73.66,9.53 66.04,9.53 63.5,12.06 62.23,12.06 59.69,12.06 59.69,13.97 55.25,13.97
A0
  Top 0.406: IC5.33 74.3,57.78 74.3,65.41 69.21,65.41 61.59,73.03 56.52,73.03 55.88,73.66 55.88,75.56 55.25,76.2 51.44,76.2 50.8,75.56 50.8,69.85 50.16,69.22 23.49,69.22 15.88,76.83 ST1.A21
A1  (via drill 0.81)
  Top 0.406: v69.85,64.14 69.21,64.14 62.87,70.48 56.52,70.48 55.25,71.75 55.25,74.93 54.61,75.56 52.07,75.56 51.44,74.93 51.44,69.22 50.8,68.58 22.86,68.58 17.15,74.3 ST1.A20
  Bottom 0.406: v69.85,64.14 70.48,64.14 71.75,62.87 73.66,62.87 74.3,62.23 74.3,60.33 IC5.34
A2  (via drill 0.81)
  Top 0.406: v22.23,84.45 38.73,84.45 40.01,85.72 IC2.1 | v17.15,71.12 15.24,71.12 14.61,71.75 ST1.A19
  Bottom 0.406: v17.15,71.12 17.15,75.56 22.23,80.64 v22.23,84.45
A4  (via drill 0.81)
  Top 0.406: v19.69,67.31 12.7,67.31 12.06,66.67 ST1.A17 | v24.77,74.3 38.73,74.3 40.01,75.56 IC2.5
  Bottom 0.406: v24.77,74.3 23.49,74.3 21.59,72.39 21.59,69.22 v19.69,67.31
A5  (via drill 0.81)
  Top 0.406: v20.95,64.77 12.7,64.77 12.06,64.14 ST1.A16 | v24.77,71.75 31.12,71.75 32.39,70.48 IC1.8
  Bottom 0.406: v24.77,71.75 24.13,71.12 24.13,67.94 v20.95,64.77
A7  (via drill 0.81)
  Top 0.406: v18.41,60.96 14.61,60.96 12.7,59.05 ST1.A14 | v24.77,79.38 31.12,79.38 32.39,80.64 IC1.12
  Bottom 0.406: v24.77,79.38 19.69,74.3 19.69,69.22 18.41,67.94 v18.41,60.96
A_CHANNEL  (via drill 0.81)
  Top 0.406: v121.92,31.11 122.55,31.11 126.47,35.03 A_CHANNEL.7
  Bottom 0.406: v121.92,31.11 121.92,17.14 118.11,13.34 JB-A3.18 116.2,12.06 113.66,12.06 JB-A3.19
A_CHANNEL1  (via drill 0.81)
  Top 0.406: v121.92,78.11 125.41,74.61 | 125.41,74.61 125.63,74.4 | B_CHANNEL.7 125.41,74.4 125.41,74.61
  Bottom 0.406: v121.92,78.11 121.92,71.75 118.11,67.94 JB-B3.18 116.2,66.67 113.66,66.67 JB-B3.19
BUS0  (via drill 0.81)
  Top 0.406: v39.37,33.02 52.71,33.02 52.71,26.04 IC5.20
  Bottom 0.406: ST1.B7 15.24,41.27 17.78,38.73 17.78,34.92 25.4,34.92 27.3,33.02 v39.37,33.02
D0  (via drill 0.81)
  Top 0.406: v66.04,53.98 64.77,55.24 56.52,55.24 55.88,55.88 50.8,55.88 50.16,56.52 25.4,56.52 22.23,53.34 22.23,43.81 17.78,39.37 17.78,34.92 16.51,33.66 ST1.A4
  Bottom 0.406: v66.04,53.98 66.04,69.85 70.48,74.3 IC5.40
D1  (via drill 0.81)
  Top 0.406: v60.33,50.16 56.52,50.16 55.25,51.44 25.4,51.44 23.49,49.53 23.49,42.55 19.05,38.1 19.05,33.66 16.51,31.11 ST1.A3
  Bottom 0.406: v60.33,50.16 60.33,53.34 60.96,53.98 60.96,71.12 IC5.1
D2  (via drill 0.81)
  Top 0.406: v66.67,42.55 53.98,42.55 52.71,43.81 52.71,45.72 52.07,46.35 25.4,46.35 24.77,45.72 24.77,41.27 20.32,36.83 20.32,32.38 16.51,28.57 ST1.A2
  Bottom 0.406: v66.67,42.55 66.67,50.16 69.85,53.34 69.85,54.61 67.31,57.15 67.31,64.14 71.12,67.94 73.66,67.94 74.3,68.58 74.3,70.48 IC5.39
D3  (via drill 0.81)
  Top 0.406: v13.97,29.84 16.51,29.84 19.69,33.02 19.69,37.47 24.13,41.91 24.13,47.62 25.4,48.9 50.16,48.9 52.07,50.8 54.61,50.8 56.52,48.9 56.52,47.62 v59.05,47.62
  Bottom 0.406: v13.97,29.84 12.7,28.57 ST1.B2 | v59.05,47.62 59.05,53.98 60.33,55.24 60.33,69.22 IC5.2
D4  (via drill 0.81)
  Top 0.406: v13.97,32.38 16.51,32.38 18.41,34.29 18.41,38.73 22.86,43.18 22.86,51.44 25.4,53.98 50.16,53.98 51.44,52.7 67.31,52.7 v68.58,53.98
  Bottom 0.406: v13.97,32.38 12.7,31.11 ST1.B3 | v68.58,53.98 66.67,55.88 66.67,65.41 70.48,69.22 IC5.38
D5  (via drill 0.81)
  Top 0.406: v13.97,34.92 16.51,34.92 17.15,35.56 17.15,40.01 21.59,44.45 21.59,55.88 24.77,59.05 49.53,59.05 50.8,57.78 v59.05,57.78
  Bottom 0.406: v13.97,34.92 12.7,33.66 ST1.B4 | v59.05,57.78 59.69,58.42 59.69,67.31 IC5.3
D6  (via drill 0.81)
  Top 0.406: v15.88,36.83 16.51,37.47 16.51,40.64 20.95,45.09 20.95,56.52 24.13,59.69 50.16,59.69 50.8,59.05 54.61,59.05 55.88,60.33 68.58,60.33 v69.85,59.05
  Bottom 0.406: v15.88,36.83 13.34,36.83 12.7,36.2 ST1.B5 | v69.85,59.05 71.12,57.78 73.66,57.78 74.93,59.05 74.93,62.87 74.3,63.5 74.3,65.41 IC5.37
D7  (via drill 0.81)
  Top 0.406: v13.34,40.01 13.34,41.91 20.32,48.9 20.32,57.15 23.49,60.33 v52.71,60.33 | v52.71,64.14 54.61,64.14 57.15,66.67 IC5.4
  Bottom 0.406: v13.34,40.01 13.34,39.37 12.7,38.73 ST1.B6 | v52.71,60.33 v52.71,64.14
EXTINT  (via drill 0.81)
  Top 0.406: v13.97,73.03 17.15,73.03 22.23,67.94 51.44,67.94 52.07,68.58 52.07,73.66 v52.71,74.3
  Bottom 0.406: v13.97,73.03 12.7,71.75 ST1.B19 | v52.71,74.3 54.61,74.3 56.52,72.39 56.52,65.41 IC5.5
GND  (via drill 0.81)
  Top 0.406: 136.47,32.28 136.53,32.23 | 136.53,71.65
  Top 1.27: 18.41,79.38 v19.69,80.64 v19.69,83.19 19.69,85.09 24.13,89.53 v58.42,89.53 59.69,89.53 | 26.67,44.45 v26.67,42.55 v26.67,40.64 39.37,40.64 | 39.37,40.64 41.27,40.64 IC3.7 | v17.78,43.81 15.24,41.27 15.24,38.73 12.7,36.2 ST1.A5 | 59.69,89.53 v59.69,90.17 | 59.69,89.53 v60.96,89.53 69.85,89.53 | 69.85,89.53 v78.1,89.53 v81.91,89.53 v81.91,91.44 81.91,90.81 78.1,90.81 | 71.12,90.81 69.85,89.53 | 78.1,90.81 71.12,90.81 | v78.1,91.44 78.1,90.81 | 78.1,99.69 v78.1,100.33 | 78.1,99.69 v78.1,99.06 | v40.01,99.06 40.01,99.69 | 40.01,99.69 v40.01,100.33 | v43.18,42.55 IC3.7 | IC3.7 39.37,40.64 | 71.12,90.81 IC4.12 | 78.1,99.69 C11.1 40.01,99.69 | v62.23,51.44 IC5.31 | 136.53,71.75 136.53,71.65 B_CHANNEL.8 | 127.64,40.64 127.64,39.89 128.38,39.14 A_CHANNEL.1 | 127.64,80.01 127.64,79.26 128.38,78.51 B_CHANNEL.1 | IC8.7 95.25,54.61 v91.44,54.61 91.44,52.7 90.8,52.07 83.82,52.07 | 83.82,52.07 82.55,52.07 IC6.7 81.91,53.98 83.82,52.07 | IC9.7 95.25,27.94 92.71,27.94 v92.07,28.57 | ST1.B22 15.88,79.38 | A_CHANNEL.8 136.47,32.28
  Bottom 0.406: 54.29,9.21 arc90 C7.1 | 62.23,14.61 62.23,6.99
  Bottom 1.27: 15.56,79.38 18.41,79.38 v19.69,80.64 v19.69,83.19 19.69,85.09 24.13,89.53 27.94,89.53 | 15.56,56.52 19.05,56.52 19.05,43.81 v17.78,43.81 | 27.94,89.53 27.94,70.48 IC1.7 26.04,62.87 C3.1 | 43.18,70.48 IC2.7 | 43.18,70.48 43.18,89.53 40.01,89.53 | v43.18,42.55 43.18,62.87 | 43.18,62.87 43.18,70.48 | 40.01,89.53 27.94,89.53 | v40.01,100.33 45.72,100.33 IC4.23 45.72,110.49 78.1,110.49 | 83.82,47.62 83.82,27.3 82.55,27.3 | 83.82,53.98 83.82,47.62 | 82.55,27.3 IC7.7 | v62.23,51.44 62.23,20.95 59.69,20.95 C8.2 | 45.72,38.1 43.18,40.64 v43.18,42.55 | v43.18,42.55 IC3.7 | 45.72,38.1 53.98,38.1 53.98,47.94 C5.1 | 78.1,110.49 v78.1,100.33 78.1,99.69 | 78.1,110.49 111.12,110.49 JB-M.2 JB-M.5 | 40.01,89.53 v40.01,99.06 v40.01,100.33 | 83.82,53.98 IC6.7 | 78.1,90.81 v78.1,89.53 v81.91,89.53 | 78.1,90.81 v78.1,91.44 v78.1,99.06 78.1,99.69 | 81.91,90.81 v81.91,89.53 | 81.91,90.81 v81.91,91.44 | 78.1,90.81 81.91,90.81 | 129.54,78.42 129.86,78.42 | 83.82,53.98 83.82,73.03 C14.1 C13.1 C12.1 81.91,83.5 v81.91,89.53 | 15.56,79.38 15.56,56.52 | v58.42,89.53 59.69,89.53 | 59.69,89.53 v59.69,90.17 | 59.69,89.53 v60.96,89.53 | 82.55,27.3 C15.1 C16.1 C17.1 82.55,6.35 | 43.18,62.87 C4.1 | 83.82,47.62 C18.1 | C11.1 78.1,99.69 | v40.01,100.33 40.01,112.39 | 62.23,5.08 62.23,6.99 C9.1 62.23,14.61 59.69,14.61 C8.2 | C8.2 C6.1 50.8,17.78 | v92.07,28.57 91.44,29.21 v91.44,54.61 | 15.56,79.38 ST1.B22 | 15.56,56.52 ST1.B13 | 45.72,38.1 DC1.15 45.72,17.78 | 45.72,9.21 45.72,3.81 | 45.72,9.21 DC1.10 45.72,17.78 | 45.72,9.21 50.8,9.21 | 50.8,9.21 54.29,9.21 | 50.8,9.21 DC1.12 50.8,17.78 | 50.8,17.78 DC1.13 | 35.56,9.21 45.72,9.21 | 35.56,9.21 DC2.5 | 35.56,9.21 27.94,9.21 DC1.3 27.94,18.41
  Bottom 1.27: 27.94,18.41 DC2.2 27.94,23.5 | 27.94,23.5 DC1.22 | 45.72,17.78 50.8,17.78 | 27.94,23.5 29.21,23.5 29.21,18.41 27.94,18.41
  other vias: 19.69,111.76 17.78,110.49 17.78,107.95 19.69,109.22 19.69,106.68 19.69,85.72 17.78,84.45 17.78,81.92 130.81,10.16 130.81,12.7 130.81,15.24 129.54,13.97 129.54,11.43 130.81,104.78 130.81,102.23 130.81,99.69 130.81,97.16 129.54,103.5 129.54,100.97 129.54,98.42
  pour Top (isolate 0.61, no thermals): 126.36,90.17 126.36,106.05 127.64,107.31 130.18,107.31 131.45,106.05 131.45,92.08 132.08,91.44 137.16,91.44 138.43,90.17 138.43,16.51 137.16,15.24 132.08,15.24 131.45,14.61 131.45,8.89 130.18,7.62 127.64,7.62 126.36,8.89 126.36,16.51 127.64,17.78 132.72,17.78 133.99,19.05 133.99,39.37 133.35,39.93 130.81,39.93 129.86,39.05 128.27,39.05 127.64,39.69 127.64,41.27 132.72,41.27 133.99,42.55 133.99,78.74 133.35,79.26 130.81,79.26 129.86,78.42 128.27,78.42 127.64,79.06 127.64,80.64 132.72,80.64 133.99,81.92 133.99,87.63 132.72,88.9 127.64,88.9
  pour Top (isolate 0.61, no thermals): 12.06,79.38 13.34,80.64 13.34,112.39 15.24,114.3 31.75,114.3 33.02,113.03 33.02,105.41 31.75,104.14 31.75,96.52 33.02,95.25 33.02,91.44 34.93,89.53 24.13,89.53 20.95,86.36 20.95,80.01 19.69,78.74 12.7,78.74
  pour Bottom (isolate 0.61, no thermals): 12.06,79.38 13.34,80.64 13.34,112.39 15.24,114.3 123.19,114.3 125.09,112.39 125.09,109.22 127,106.68 126.36,106.05 124.46,106.05 122.55,107.95 116.2,107.95 114.3,109.86 45.72,109.86 44.45,111.12 33.66,111.12 33.02,110.49 33.02,105.41 31.75,104.14 31.75,96.52 33.02,95.25 33.02,91.44 34.93,89.53 24.77,89.53 20.95,85.72 20.95,81.28 18.41,78.74 12.7,78.74
  pour Bottom (isolate 0.61, no thermals): 133.99,39.37 133.99,25.72 132.72,24.45 127.95,24.45 126.36,22.86 126.36,7.94 130.18,7.94 131.45,9.21 131.45,14.61 132.08,15.24 137.16,15.24 138.43,16.51 138.43,90.17 137.16,91.44 132.08,91.44 131.45,92.08 131.45,106.05 130.18,107.31 125.73,107.31 124.46,106.05 124.46,92.08 127.32,89.22 127.32,79.06 128.27,78.11 129.54,78.11 130.81,79.38 133.35,79.38 133.99,78.74 133.67,65.09 132.4,63.82 128.27,63.82 127.32,62.87 127.32,39.69 128.27,38.73 129.22,38.73 130.49,40.01 133.35,40.01
  pour Top (isolate 0.61): 26.67,44.45 31.75,44.45 35.56,40.64 26.67,40.64
  pour Bottom (isolate 0.61, no thermals): 20.64,11.43 20.64,29.84 21.59,30.8 27.62,30.8 27.62,31.11 26.99,31.11 24.77,33.34 16.83,33.34 15.88,32.38 15.88,28.89 16.83,27.94 17.78,27.94 18.41,27.3 18.41,25.08 17.46,24.13 14.92,24.13 13.34,22.23 13.34,3.17 15.24,1.27 123.19,1.27 125.09,3.17 125.09,6.67 126.36,7.94 126.36,16.19 118.11,7.62 110.49,7.62 104.77,13.34 92.07,13.34 88.27,9.53 82.55,9.53 80.01,6.99 75.56,6.99 73.02,4.45 69.53,4.45 66.99,6.99 56.83,6.99 54.61,9.53 22.54,9.53
  pour Bottom (isolate 0.61, no thermals): 15.88,55.88 15.88,59.05 19.69,59.05 26.04,65.41 26.04,45.09 27.3,43.81 27.38,38.89 19.76,38.89 19.69,40.01 17.78,41.91 17.78,53.98
  pour Bottom (no thermals): 27.62,18.73 40.64,18.73 40.64,23.18 27.62,23.18 27.62,31.11 43.5,31.11 45.72,33.34 46.04,33.34 46.04,26.67 50.8,26.67 50.8,15.88 46.04,15.88 46.04,8.89 27.62,9.21
  pour Bottom: 57.79,17.78 60.01,17.78 60.01,15.24 64.13,15.24 64.13,20.32 59.69,20.32 59.69,18.41 57.79,18.41 57.79,23.5 59.69,25.4 59.69,36.2 62.23,38.73 62.23,42.55 64.77,40.01 68.26,40.01 69.21,39.05 69.21,38.1 71.12,36.2 71.12,25.08 72.07,24.13 73.34,24.13 74.3,23.18 74.3,11.11 78.42,6.99 75.25,6.99 73.34,8.89 69.53,8.89 67.63,6.99 62.23,6.99 62.23,14.29 59.37,14.29 57.79,15.88
IEI  (via drill 0.81)
  Top 0.406: v13.97,63.5 21.59,63.5 24.13,66.04 53.34,66.04 55.25,67.94 v55.25,69.22
  Bottom 0.406: v13.97,63.5 12.06,61.59 ST1.B15 | v55.25,69.22 55.25,64.77 56.52,63.5 56.52,62.87 IC5.6
IEO  (via drill 0.81)
  Top 0.406: v13.97,66.04 20.95,66.04 21.59,66.67 52.71,66.67 53.98,67.94 v53.98,70.48
  Bottom 0.406: v13.97,66.04 12.06,64.14 ST1.B16 | v53.98,70.48 53.98,64.14 55.88,62.23 55.88,60.96 IC5.7
IORQ  (via drill 0.81)
  Top 0.406: v13.97,51.44 15.88,51.44 18.41,53.98 18.41,59.05 24.77,65.41 54.61,65.41 57.15,67.94 64.13,67.94 69.21,62.87 71.75,62.87 IC5.36
  Bottom 0.406: ST1.B11 v13.97,51.44
M1  (via drill 0.81)
  Top 0.406: v13.97,45.72 15.88,45.72 19.69,49.53 19.69,57.78 22.86,60.96 49.53,60.96 50.16,61.59 v53.98,61.59
  Bottom 0.406: v13.97,45.72 13.97,45.09 12.7,43.81 ST1.B8 | v53.98,61.59 53.98,60.33 IC5.8
N$1
  Top 0.406: R3.1 60.33,78.11 IC2.11 IC2.4 IC1.11 IC1.4
  Bottom 0.406: IC3.11 50.16,51.44 50.16,76.83 IC2.11 | IC1.11 IC1.10 | IC2.4 IC2.3
N$2
  Top 0.406: IC5.21 71.75,27.3 55.88,27.3 53.98,29.21 53.98,38.73 50.16,42.55 IC3.8
N$3  (via drill 0.81)
  Top 0.406: v75.56,107.95 77.47,107.95 80.01,105.41 JP2.20 JP2.18 JP2.16 JP2.14 JP2.12 JP2.10 JP2.8 JP2.6 JP2.4 JP2.2
  Bottom 0.406: v75.56,107.95 74.93,107.95 67.31,100.33 67.31,88.27 64.77,85.72 64.77,78.74 66.04,77.47 71.75,77.47 74.93,74.3 74.93,67.31 76.83,65.41 76.83,45.09 IC5.27
N$4  (via drill 0.81)
  Top 0.406: v52.07,101.6 76.2,101.6 76.83,102.23 78.1,102.23 80.64,99.69 JP1.20 | v50.16,43.81 51.44,43.81 53.98,41.27 IC5.14
  Bottom 0.406: v52.07,101.6 52.07,87.63 50.8,86.36 50.8,46.99 50.16,46.35 v50.16,43.81 | JP1.20 JP1.18 JP1.16 JP1.14 JP1.12 JP1.10 JP1.8 JP1.6 JP1.4 JP1.2 | IC5.14 IC5.13
N$5
  Top 0.406: IC4.20 53.34,105.41 52.71,104.78 41.27,104.78 38.1,101.6 38.1,98.42 37.47,97.79 R1.1 33.15,97.79 33.15,97.92 X-TAL.1
  Bottom 0.406: R1.1 37.47,96.52 C21.2
N$6
  Top 0.406: IC4.21 49.53,105.41 38.73,105.41 R1.2 34.29,102.87 34.16,102.74 X-TAL.2
  Bottom 0.406: R1.2 37.47,104.14 C20.2
N$7
  Top 0.406: DIP_SW.12 R7.7
  Bottom 0.406: R7.7 37.47,80.64 40.01,83.19 IC2.2
N$8  (via drill 0.81)
  Top 0.406: v40.01,79.38 46.36,79.38 47.62,80.64 IC2.12 | DIP_SW.11 R7.6
  Bottom 0.406: v40.01,79.38 38.73,78.11 38.73,56.52 R7.6
N$9
  Top 0.406: DIP_SW.10 R7.5
  Bottom 0.406: R7.5 40.01,55.24 40.01,71.75 IC2.6
N$10
  Top 0.406: DIP_SW.9 R7.4
  Bottom 0.406: IC1.9 34.93,71.75 34.93,51.44 DIP_SW.9
N$11  (via drill 0.81)
  Top 0.406: v34.93,76.83 32.39,76.83 31.12,75.56 IC1.5 | DIP_SW.8 R7.3
  Bottom 0.406: v34.93,76.83 35.56,76.2 35.56,49.53 DIP_SW.8
N$12
  Top 0.406: DIP_SW.7 R7.2
  Bottom 0.406: IC1.13 36.2,80.64 36.2,47.62 DIP_SW.7
N$13
  Bottom 0.406: C15.2 77.47,31.11 78.74,32.38 IC7.5
N$14  (via drill 0.81)
  Top 0.406: v79.38,31.11 84.45,31.11 85.72,29.84 IC7.9
  Bottom 0.406: v79.38,31.11 79.38,16.51 C16.2
N$15
  Bottom 0.406: C17.2 75.56,12.7 75.56,30.48 78.74,33.66 78.74,38.1 IC7.2
N$16  (via drill 0.81)
  Top 0.406: v79.38,57.78 85.72,57.78 86.99,56.52 IC6.9
  Bottom 0.406: v79.38,57.78 78.1,59.05 78.1,66.04 75.56,68.58 75.56,81.6 C12.2
N$17
  Bottom 0.406: C14.2 77.15,68.9 79.38,66.67 79.38,60.33 IC6.5
N$18
  Bottom 0.406: C13.2 79.38,75.88 79.38,67.94 IC6.2
N$19
  Top 0.406: IC4.9 63.5,92.08 64.77,93.34 97.16,93.34 102.23,98.42 102.23,100.33 JP1.1
  Bottom 0.406: JP2.1 104.77,106.68 104.77,102.87 JP1.1
N$20
  Top 0.406: IC4.13 76.83,106.68 79.38,104.14 99.69,104.14 100.96,102.87 JP1.3
  Bottom 0.406: JP2.3 102.23,106.68 102.23,102.87 JP1.3
N$21
  Top 0.406: IC4.8 60.96,92.08 62.87,93.98 95.25,93.98 99.69,98.42 99.69,100.33 JP1.5
  Bottom 0.406: JP2.5 99.69,106.68 99.69,102.87 JP1.5
N$22
  Top 0.406: IC4.7 58.42,92.08 60.96,94.61 93.34,94.61 97.16,98.42 97.16,100.33 JP1.7
  Bottom 0.406: JP2.7 97.16,106.68 97.16,102.87 JP1.7
N$23
  Top 0.406: IC4.5 53.34,92.08 56.52,95.25 91.44,95.25 94.61,98.42 94.61,100.33 JP1.9
  Bottom 0.406: JP2.9 94.61,106.68 94.61,102.87 JP1.9
N$24
  Top 0.406: IC4.4 50.8,92.08 54.61,95.89 89.53,95.89 92.07,98.42 92.07,100.33 JP1.11
  Bottom 0.406: JP2.11 92.07,106.68 92.07,102.87 JP1.11
N$25
  Top 0.406: IC4.15 67.31,105.41 71.75,105.41 72.39,106.05 76.2,106.05 79.38,102.87 86.99,102.87 JP1.13
  Bottom 0.406: JP2.13 89.53,106.68 89.53,102.87 JP1.13
N$26
  Top 0.406: IC4.3 48.26,92.08 52.71,96.52 85.09,96.52 86.99,98.42 86.99,100.33 JP1.15
  Bottom 0.406: JP2.15 86.99,106.68 86.99,102.87 JP1.15
N$27
  Top 0.406: IC4.2 45.72,92.08 50.8,97.16 83.18,97.16 84.45,98.42 84.45,100.33 JP1.17
  Bottom 0.406: JP2.17 84.45,106.68 84.45,102.87 JP1.17
N$28
  Top 0.406: IC4.1 43.18,92.08 48.9,97.79 81.28,97.79 81.91,98.42 81.91,100.33 JP1.19
  Bottom 0.406: JP2.19 81.91,106.68 81.91,102.87 JP1.19
N$29  (via drill 0.81)
  Top 0.406: v67.94,45.09 53.98,45.09 53.34,45.72 53.34,46.35 52.71,46.99 50.8,46.99 50.16,47.62 IC3.10
  Bottom 0.406: v67.94,45.09 67.94,50.16 70.48,52.7 70.48,55.24 67.94,57.78 67.94,61.59 69.21,62.87 70.48,62.87 71.75,61.59 IC5.35
N$30  (via drill 0.81)
  Top 0.406: IC4.22 49.53,107.95 v64.77,107.95
  Bottom 0.406: v64.77,107.95 64.77,92.71 IC4.10 61.59,87 R2.1
N$31  (via drill 0.81)
  Top 0.406: v94.61,26.04 106.05,26.04 107.31,24.77 107.31,16.51 109.22,14.61 113.66,14.61 JB-A3.14
  Bottom 0.406: v94.61,26.04 94.61,28.57 IC9.6
N$32
  Top 0.406: L1.1
  Top 1.27: DC1.1 22.86,18.41 DC2.1 22.86,23.5 DC1.24 22.86,29.53 L1.1
N$33  (via drill 0.81)
  Top 0.406: v95.25,92.08 98.42,92.08 102.23,95.89 JB-B1.1 113.66,94.61 116.2,94.61 JB-B1.6
  Bottom 0.406: v95.25,92.08 95.25,71.12 94.61,70.48 94.61,67.94 IC8.2
N$34  (via drill 0.81)
  Top 0.406: v91.44,65.41 v97.16,65.41 100.96,65.41 102.23,64.14 IC8.12 | v97.16,38.73 99.69,38.73 100.96,40.01 IC9.13
  Bottom 0.406: v97.16,65.41 97.16,62.87 IC8.4 94.61,60.33 94.61,51.44 93.34,50.16 93.34,40.01 94.61,38.73 v97.16,38.73 97.16,33.66 IC9.5 | v91.44,65.41 91.44,76.2 R4.1
N$35  (via drill 0.81)
  Top 0.406: v93.34,23.5 104.77,23.5 106.05,22.23 106.05,12.7 109.22,9.53 113.66,9.53 JB-A3.20
  Bottom 0.406: v93.34,23.5 93.34,34.92 IC9.3
N$37  (via drill 0.81)
  Top 0.406: v121.92,36.2 122.55,36.2 124.13,37.77 A_CHANNEL.6
  Bottom 0.406: v121.92,36.2 123.19,34.92 123.19,15.88 118.11,10.79 JB-A3.21 115.57,8.89 111.76,8.89 111.12,9.53 111.12,12.06 JB-A3.16
N$38  (via drill 0.81)
  Top 0.406: v89.53,28.57 89.53,27.3 92.07,24.77 105.41,24.77 106.68,23.5 106.68,14.61 109.22,12.06 113.66,12.06 JB-A3.17 | v89.53,33.66 85.72,33.66 84.45,34.92 IC7.4
  Bottom 0.406: v89.53,33.66 v89.53,28.57
N$39
  Top 0.406: JB-A3.8 113.66,19.68 109.22,19.68 107.95,20.95 107.95,26.04 106.68,27.3 IC9.8
N$40
  Top 0.406: JB-A3.2 113.66,24.77 111.12,24.77 110.49,25.4 110.49,33.66 109.22,34.92 IC9.11
N$41
  Top 0.406: A_CHANNEL.3 127,33.66 120.02,26.67 120.02,24.77 118.74,23.5 JB-A3.6
  Bottom 0.406: JB-A3.6 116.2,22.23 111.76,22.23 111.12,22.86 111.12,24.77 JB-A3.1
N$42
  Top 0.406: A_CHANNEL.2 124.66,36.4 119.38,31.11 119.38,26.67 118.74,26.04 JB-A3.3
  Bottom 0.406: JB-A3.4 113.66,24.77 116.2,24.77 JB-A3.3
N$43  (via drill 0.81)
  Top 0.406: v109.22,22.23 113.03,22.23 114.3,23.5 JB-A3.5 | v107.31,43.81 85.72,43.81 84.45,42.55 IC7.1
  Bottom 0.406: v107.31,43.81 107.31,36.2 107.95,35.56 107.95,23.5 v109.22,22.23
N$44  (via drill 0.81)
  Top 0.406: v109.22,17.14 113.66,17.14 JB-A3.11 | v106.68,33.66 94.61,33.66 93.34,32.38 IC7.10
  Bottom 0.406: v106.68,33.66 106.68,19.68 v109.22,17.14
N$45  (via drill 0.81)
  Top 0.406: A_CHANNEL.4 126.16,30.91 121.28,26.04 121.28,23.5 118.74,20.95 JB-A3.9 | JB-A1.7 113.66,33.66 116.2,33.66 116.2,31.11 117.47,29.84 v117.47,28.57
  Bottom 0.406: v117.47,28.57 118.74,27.3 118.74,22.23 JB-A3.9
N$46
  Top 0.406: A_CHANNEL.5 125.32,28.17 121.92,24.77 121.92,21.59 118.74,18.41 JB-A3.12
  Bottom 0.406: JB-A1.11 114.93,31.75 116.2,30.48 117.47,30.48 119.38,28.57 119.38,20.32 JB-A3.12
N$47
  Top 0.406: JB-A3.15 118.74,15.88 122.55,19.68 122.55,23.5 125.73,26.67 130.65,26.67 132.56,28.57 A_CHANNEL.9
  Bottom 0.406: JB-A1.9 120.65,31.75 120.65,17.78 118.74,15.88 JB-A3.15
N$48
  Bottom 0.406: JB-A1.12 120.02,29.84 120.02,19.05 118.11,17.14 113.66,17.14 JB-A3.13
N$49
  Top 0.406: IC5.15 68.58,38.73 69.85,37.47 78.1,37.47 79.38,36.2 99.69,36.2 100.96,37.47 IC9.12
N$50
  Top 0.406: JB-A1.10 116.2,28.57 116.2,22.23 114.3,22.23 113.03,20.95 JB-A3.7
N$51
  Bottom 0.406: JB-A3.10 110.49,20.32 110.49,27.94 113.66,31.11 113.66,33.66 JB-A1.8
N$52  (via drill 0.81)
  Top 0.406: v56.52,40.01 76.83,40.01 79.38,37.47 IC7.3
  Bottom 0.406: v56.52,40.01 56.52,45.09 IC5.12
N$53
  Top 0.406: IC5.17 68.58,33.66 69.85,34.92 78.1,34.92 79.38,33.66 83.18,33.66 85.72,31.11 99.69,31.11 100.96,32.38 IC9.10
N$54
  Top 0.406: JB-A1.3 118.74,38.73 118.74,36.2 100.96,36.2 99.69,34.92 IC9.4
N$55
  Top 0.406: IC5.18 68.58,31.11 69.85,29.84 76.83,29.84 78.1,28.57 84.45,28.57 85.72,27.3 IC7.8
N$56
  Top 0.406: IC5.19 57.15,28.57 56.52,29.21 56.52,31.75 57.15,32.38 75.56,32.38 78.1,29.84 IC7.6
N$57
  Top 0.406: JB-A1.1 108.58,40.01 107.31,41.27 100.96,41.27 99.69,40.01 IC9.2
  Bottom 0.406: JB-A1.6 116.2,38.73 113.66,38.73 JB-A1.1
N$58  (via drill 0.81)
  Top 0.406: v60.33,46.35 67.94,46.35 71.75,50.16 76.83,50.16 77.47,50.8 107.31,50.8 114.93,43.18 JB-A1.2
  Bottom 0.406: v60.33,46.35 60.33,38.73 IC5.16
N$59  (via drill 0.81)
  Top 0.406: v23.49,81.92 46.36,81.92 47.62,83.19 IC2.13 | v18.41,69.85 13.34,69.85 12.7,69.22 ST1.A18
  Bottom 0.406: v18.41,69.85 18.41,74.93 23.49,80.01 v23.49,81.92
N$60  (via drill 0.81)
  Top 0.406: v19.69,62.23 12.7,62.23 12.06,61.59 ST1.A15
  Bottom 0.406: v19.69,62.23 19.69,65.41 22.86,68.58 22.86,71.75 24.13,73.03 IC1.6
N$61  (via drill 0.81, 1.02 pad 1.42)
  Top 0.406: v111.76,59.05 112.39,58.42 118.11,58.42 118.74,57.78 v118.74,56.52
N$62  (via drill 1.02 pad 1.42)
  other vias: 97.16,78.11
N$63  (via drill 1.02 pad 1.42)
  Top 0.406: v102.23,74.3 102.23,75.56 101.6,76.2 95.88,76.2 95.25,76.83 95.25,80.64 93.98,81.92 v93.34,81.92
N$64  (via drill 1.02 pad 1.42)
  other vias: 97.16,81.92
N$65  (via drill 0.81, 1.02 pad 1.42)
  Top 0.406: v121.92,83.82 105.41,83.82 103.5,85.72 v102.23,85.72
N$66  (via drill 1.02 pad 1.42)
  other vias: 97.16,85.72
N$67  (via drill 0.81)
  Top 0.406: v104.77,97.16 116.2,97.16 JB-B1.3
  Bottom 0.406: v104.77,97.16 104.77,67.94 IC8.13
N$68  (via drill 1.02 pad 1.42)
  other vias: 113.66,60.33
N$69  (via drill 1.02 pad 1.42)
  other vias: 113.66,56.52
N$70  (via drill 1.02 pad 1.42)
  other vias: 113.66,52.7
N$71  (via drill 1.02 pad 1.42)
  other vias: 113.66,47.62
N$72  (via drill 1.02 pad 1.42)
  other vias: 116.2,47.62
N$73  (via drill 1.02 pad 1.42)
  other vias: 118.74,47.62
N$74  (via drill 1.02 pad 1.42)
  other vias: 118.74,52.7
N$75
  Top 0.406: R6.1 116.84,102.87 110.49,102.87 108.58,104.78 JB-M.4
  Bottom 0.406: JB-M.4 108.58,94.61 107.31,93.34 107.31,73.03 109.22,71.12 109.22,54.61 107.31,52.7 106.05,52.7 105.41,53.34 105.41,57.15 IC8.10
N$76  (via drill 1.02 pad 1.42)
  other vias: 118.74,60.33
N$77  (via drill 0.81)
  Top 0.406: v56.52,37.47 67.31,37.47 v68.58,36.2
N$78  (via drill 1.02 pad 1.42)
  other vias: 102.23,89.53
N$79  (via drill 0.81)
  other vias: 112.39,50.16
N$80
  Top 0.406: R5.1 116.2,106.68 109.85,106.68 JB-M.1
  Bottom 0.406: JB-M.1 106.68,106.05 106.68,94.61 106.05,93.98 106.05,73.03 105.41,72.39 105.41,60.96 104.77,60.33 102.87,60.33 102.23,59.69 102.23,50.16 103.5,48.9 103.5,48.26 104.77,46.99 104.77,31.11 IC9.9
N$81  (via drill 0.81)
  other vias: 112.39,86.36
N$82  (via drill 0.81)
  other vias: 88.27,86.36
N$83  (via drill 0.81, 1.02 pad 1.42)
  Top 0.406: v88.27,88.27 v90.8,88.27
N$84  (via drill 0.81)
  Top 0.406: v93.34,52.7 108.58,52.7 110.49,54.61 110.49,62.23 112.39,64.14 113.66,64.14 JB-B3.20
  Bottom 0.406: v93.34,52.7 93.34,61.59 IC8.3
N$85  (via drill 0.81)
  Top 0.406: v122.55,82.07 122.55,81.28 126.69,77.14 B_CHANNEL.6
  Bottom 0.406: v122.55,82.07 123.19,81.44 123.19,80.96 123.19,70.48 118.11,65.41 JB-B3.21 116.2,64.14 111.12,64.14 111.12,66.67 JB-B3.16
N$86
  Top 0.406: JB-B3.17 113.66,66.67 111.12,66.67 110.49,66.04 110.49,63.5 109.85,62.87 109.85,59.05 108.58,57.78 90.8,57.78 89.53,59.05 IC6.10
N$87
  Top 0.406: JB-B3.14 113.66,69.22 111.12,69.22 109.85,67.94 109.85,64.14 107.31,61.59 IC8.11
N$88  (via drill 0.81)
  Top 0.406: v106.68,65.41 106.68,67.31 109.85,70.48 109.85,73.03 111.12,74.3 113.66,74.3 JB-B3.8 | IC8.8 v106.68,53.98
  Bottom 0.406: v106.68,53.98 v106.68,65.41
N$89  (via drill 0.81)
  Top 0.406: v106.68,71.12 107.31,71.12 108.58,72.39 108.58,78.11 109.85,79.38 113.66,79.38 JB-B3.2 | v107.95,55.24 102.23,55.24 100.96,56.52 IC8.6
  Bottom 0.406: v106.68,71.12 107.95,69.85 v107.95,55.24
N$90  (via drill 1.02 pad 1.42)
  Top 0.406: B_CHANNEL.3 123.82,73.03 118.74,78.11 JB-B3.6 116.2,79.38 116.2,81.92 115.57,82.55 113.03,82.55 112.39,81.92 JB-B3.1 105.41,80.64 104.14,81.92 v102.23,81.92
N$91
  Top 0.406: B_CHANNEL.2 126.16,75.77 121.28,80.64 JB-B3.3
  Bottom 0.406: JB-B3.4 113.66,79.38 116.2,79.38 JB-B3.3
N$92
  Top 0.406: JB-B3.5 113.66,76.83 111.12,76.83 109.22,74.93 109.22,71.75 105.41,67.94 86.99,67.94 85.72,69.22 IC6.1
N$93
  Top 0.406: JB-B3.11 113.66,71.75 111.12,71.75 110.49,71.12 110.49,69.85 109.22,68.58 109.22,64.77 107.31,62.87 86.99,62.87 85.72,61.59 IC6.4
N$94  (via drill 0.81, 1.02 pad 1.42)
  Top 0.406: B_CHANNEL.4 124.03,70.28 118.74,75.56 JB-B3.9 | JB-B1.7 113.03,90.81 114.3,89.53 118.74,89.53 119.38,88.9 119.38,87 v117.47,85.09 110.49,85.09 107.95,87.63 96.52,87.63 95.88,87 95.88,80.64 96.52,80.01 99.69,80.01 101.6,78.11 v102.23,78.11
  Bottom 0.406: v117.47,85.09 118.74,83.82 118.74,76.83 JB-B3.9
N$95
  Top 0.406: B_CHANNEL.5 124.23,67.54 118.74,73.03 JB-B3.12
  Bottom 0.406: JB-B1.11 116.84,86.36 118.11,86.36 119.38,85.09 119.38,74.93 JB-B3.12
N$96
  Top 0.406: JB-B3.15 118.74,70.48 123.19,66.04 130.65,66.04 132.56,67.94 B_CHANNEL.9
  Bottom 0.406: JB-B3.15 118.74,70.48 120.65,72.39 120.65,87.63 JB-B1.9
N$97
  Bottom 0.406: JB-B3.13 113.66,71.75 118.11,71.75 120.02,73.66 120.02,85.72 JB-B1.12
N$98
  Bottom 0.406: JB-B3.7 111.12,76.83 111.12,87 JB-B1.10
N$99
  Bottom 0.406: JB-B1.8 113.66,89.53 111.76,89.53 110.49,88.27 110.49,74.93 JB-B3.10
N$100  (via drill 0.81)
  Top 0.406: v71.75,45.09 75.56,45.09 80.01,49.53 89.53,49.53 90.17,48.9 v95.25,48.9
  Bottom 0.406: v71.75,45.09 71.75,40.01 IC5.26 | v95.25,48.9 97.79,51.44 97.79,57.15 IC8.5
N$101  (via drill 0.81)
  Top 0.406: v75.56,64.14 IC6.3
  Bottom 0.406: v75.56,64.14 75.56,46.35 IC5.28
N$102  (via drill 0.81)
  Top 0.406: v76.83,42.55 76.83,43.18 78.74,45.09 108.58,45.09 109.85,43.81 v109.85,42.55
  Bottom 0.406: v76.83,42.55 74.93,40.64 74.93,35.56 IC5.24 | v109.85,42.55 109.85,43.18 104.77,48.26 104.77,55.24 IC8.9
N$104
  Bottom 0.406: IC5.23 76.2,34.29 76.2,39.37 78.1,41.27 78.1,55.88 78.74,56.52 IC6.6
N$105  (via drill 0.81)
  Top 0.406: v79.38,55.24 85.72,55.24 86.99,53.98 IC6.8
  Bottom 0.406: v79.38,55.24 79.38,40.64 77.47,38.73 77.47,33.66 74.3,30.48 74.3,29.84 IC5.22
N$107  (via drill 0.81)
  Top 0.406: v70.48,46.35 71.75,47.62 76.83,47.62 79.38,50.16 104.77,50.16 v106.05,48.9
  Bottom 0.406: v70.48,46.35 70.48,38.73 IC5.25 | v106.05,48.9 109.85,52.7 109.85,71.75 109.22,72.39 109.22,92.71 111.12,94.61 113.66,94.61 JB-B1.2
N$108  (via drill 1.02 pad 1.42)
  other vias: 90.8,86.36
N$110  (via drill 1.02 pad 1.42)
  other vias: 90.8,90.17
N$111  (via drill 1.02 pad 1.42)
  other vias: 97.16,89.53
N$112  (via drill 1.02 pad 1.42)
  other vias: 88.27,81.92
RD  (via drill 0.81)
  Top 0.406: v13.97,48.9 15.88,48.9 19.05,52.07 19.05,58.42 25.4,64.77 48.9,64.77 50.8,62.87 67.94,62.87 69.21,61.59 v69.85,61.59
  Bottom 0.406: v69.85,61.59 68.58,60.33 68.58,58.42 IC5.32 | ST1.B10 v13.97,48.9
RESET  (via drill 0.81)
  Top 0.406: v13.97,68.58 20.32,68.58 21.59,67.31 52.07,67.31 52.71,67.94 52.71,71.75 v53.98,73.03 | v69.21,42.55 74.3,42.55 77.47,45.72 110.49,45.72 113.66,42.55 113.66,38.73 JB-A1.5 | JB-B1.5 113.66,92.08 v110.49,92.08 | v51.44,45.09 IC3.9
  Bottom 0.406: v13.97,68.58 12.06,66.67 ST1.B17 | v53.98,73.03 51.44,73.03 | 51.44,73.03 v51.44,45.09 | 51.44,73.03 51.44,74.93 52.07,75.56 59.05,75.56 61.59,73.03 61.59,53.98 64.13,51.44 64.13,42.55 65.41,41.27 67.94,41.27 v69.21,42.55 | v110.49,92.08 109.85,91.44 109.85,73.03 110.49,72.39 110.49,45.09 111.12,44.45 111.12,36.83 111.76,36.2 113.66,36.2 JB-A1.5
VCC  (via drill 0.6 pad 1.42, 0.81)
  Top 1.27: IC1.14 32.39,85.72 32.39,86.36 | 32.39,86.36 v32.39,87.95 32.39,87.63 40.01,87.63 | 42.55,87.63 46.99,87.63 v46.99,87.95 46.99,87 48.9,87 | 48.9,86.36 48.9,87 | v63.5,53.98 IC5.9 | 48.9,87 59.69,87 | 59.69,87 v63.5,87 v72.39,87 73.66,87 | 73.66,87 v73.66,87.63 | 73.66,87 v74.93,87 85.09,87 | 85.09,87 v86.36,87 | v41.91,102.87 41.91,103.5 75.56,103.5 C11.2 | 37.47,38.1 v37.47,38.73 37.47,38.42 | v42.55,38.1 43.5,38.1 46.99,38.1 46.99,39.37 | 46.99,39.37 v46.99,40.01 | 31.12,38.1 v31.12,38.73 | 31.12,38.1 31.12,37.78 | 31.75,38.1 v33.02,38.1 | 46.99,39.37 45.09,39.37 43.82,38.1 | 31.12,38.1 30.48,38.1 | 48.9,86.36 IC2.14 v46.99,85.72 | 48.9,86.36 59.69,86.36 59.69,87 | 48.9,86.36 43.82,86.36 42.55,87.63 | 40.01,87.63 42.55,87.63 | 40.01,87.63 38.73,86.36 32.39,86.36 | 85.09,87 v85.09,85.72 | IC4.24 43.18,108.58 | 16.51,16.51 C1.1 | v16.51,26.04 ST1.B1
  Top 1.93: 37.47,38.1 v42.55,38.1 | v16.51,26.04 16.83,26.04 16.83,26.67 22.23,32.07 22.23,35.88 24.45,38.1 31.12,38.1 | 43.5,38.1 L1.2
  Top 2.54: 31.12,38.1 31.75,38.1 37.47,38.1
  Bottom 1.27: 37.47,38.1 39.37,38.1 | 37.47,38.1 v37.47,38.73 R7.1 | 46.99,57.78 IC3.14 | 46.99,57.78 46.99,62.87 | 46.99,62.87 v46.99,87.95 | v46.99,40.01 46.99,57.78 | 31.12,85.72 33.02,85.72 | 31.12,62.87 v31.12,38.73 31.12,38.1 | 31.12,62.87 31.12,85.72 | 73.66,87 v73.66,87.63 73.66,102.87 C11.2 | 73.66,87 73.66,83.19 R2.2 R3.2 | v41.91,102.87 43.18,102.87 IC4.24 | v86.36,87 85.09,87 | 86.36,42.55 IC7.14 | 86.36,42.55 v86.36,11.43 | v63.5,87 v63.5,53.98 | 85.09,87 v83.82,87 | 85.09,87 v85.09,85.72 85.09,78.11 R4.2 v88.27,74.3 IC6.14 86.36,69.22 86.36,47.62 | 31.12,38.1 37.47,38.1 | 31.12,38.1 v33.02,38.1 | v72.39,87 73.66,87 | 73.66,87 v74.93,87 | 31.12,85.72 31.12,87.63 32.39,87.63 | 32.39,87.63 v32.39,87.95 | 32.39,87.63 33.66,87.63 IC1.14 33.02,85.72 | 33.02,85.72 33.02,87 31.75,87 | 46.99,62.87 C4.2 | 31.12,62.87 C3.2 | 86.36,47.62 C18.2 | 86.36,47.62 86.36,42.55 | IC5.9 C5.2 | ST1.B1 v16.51,26.04
  pour Top (isolate 0.61, no thermals): 42.55,106.68 46.99,110.49 120.02,110.49 121.28,109.22 121.28,91.44 121.92,90.81 121.92,89.53 122.55,88.9 124.46,88.9 125.09,89.53 125.09,112.39 123.19,114.3 43.18,114.3 42.55,113.67
  pour Top (isolate 0.61, no thermals): 12.7,25.4 12.7,26.67 13.34,27.3 18.41,27.3 19.69,26.04 19.69,8.89 21.59,6.99 62.87,6.99 65.41,4.45 69.21,4.45 71.75,6.99 83.82,6.99 85.09,8.26 85.09,11.43 86.99,13.34 102.87,13.34 108.58,7.62 118.74,7.62 120.02,8.89 120.02,13.34 120.65,13.97 124.46,13.97 125.09,13.34 125.09,3.17 123.19,1.27 15.24,1.27 13.34,3.17 13.34,24.77
  pour Bottom (isolate 0.61, no thermals): 28.58,36.83 42.55,36.83 42.55,38.1 39.37,41.27 28.58,41.27

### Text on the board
Top: NI071AC
tPlace: ver 1.0 | ON | OFF | BI | ST | 9600 | 4800 | 2400 | 1800 | 1200 | 600 | 300 | 150 | 110 | 75 | 22A | MOD | TER | 2A | 3A | 4A | 5A | 6A | 7A | BI | ST | 1A | MOD | TER
Document: MZ-1E24 | SHARP NI071AC-1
